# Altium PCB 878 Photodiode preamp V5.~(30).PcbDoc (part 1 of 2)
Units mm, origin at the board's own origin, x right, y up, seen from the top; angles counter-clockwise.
Board outline 114 x 114 mm, 6 copper layers (Top Layer, Internal Plane 1, Dummy Ground, Dummy Power, Internal Plane 2, Bottom Layer), stack 0.534 mm thick; 182 components, 80 nets, 485 pads, 76 vias.
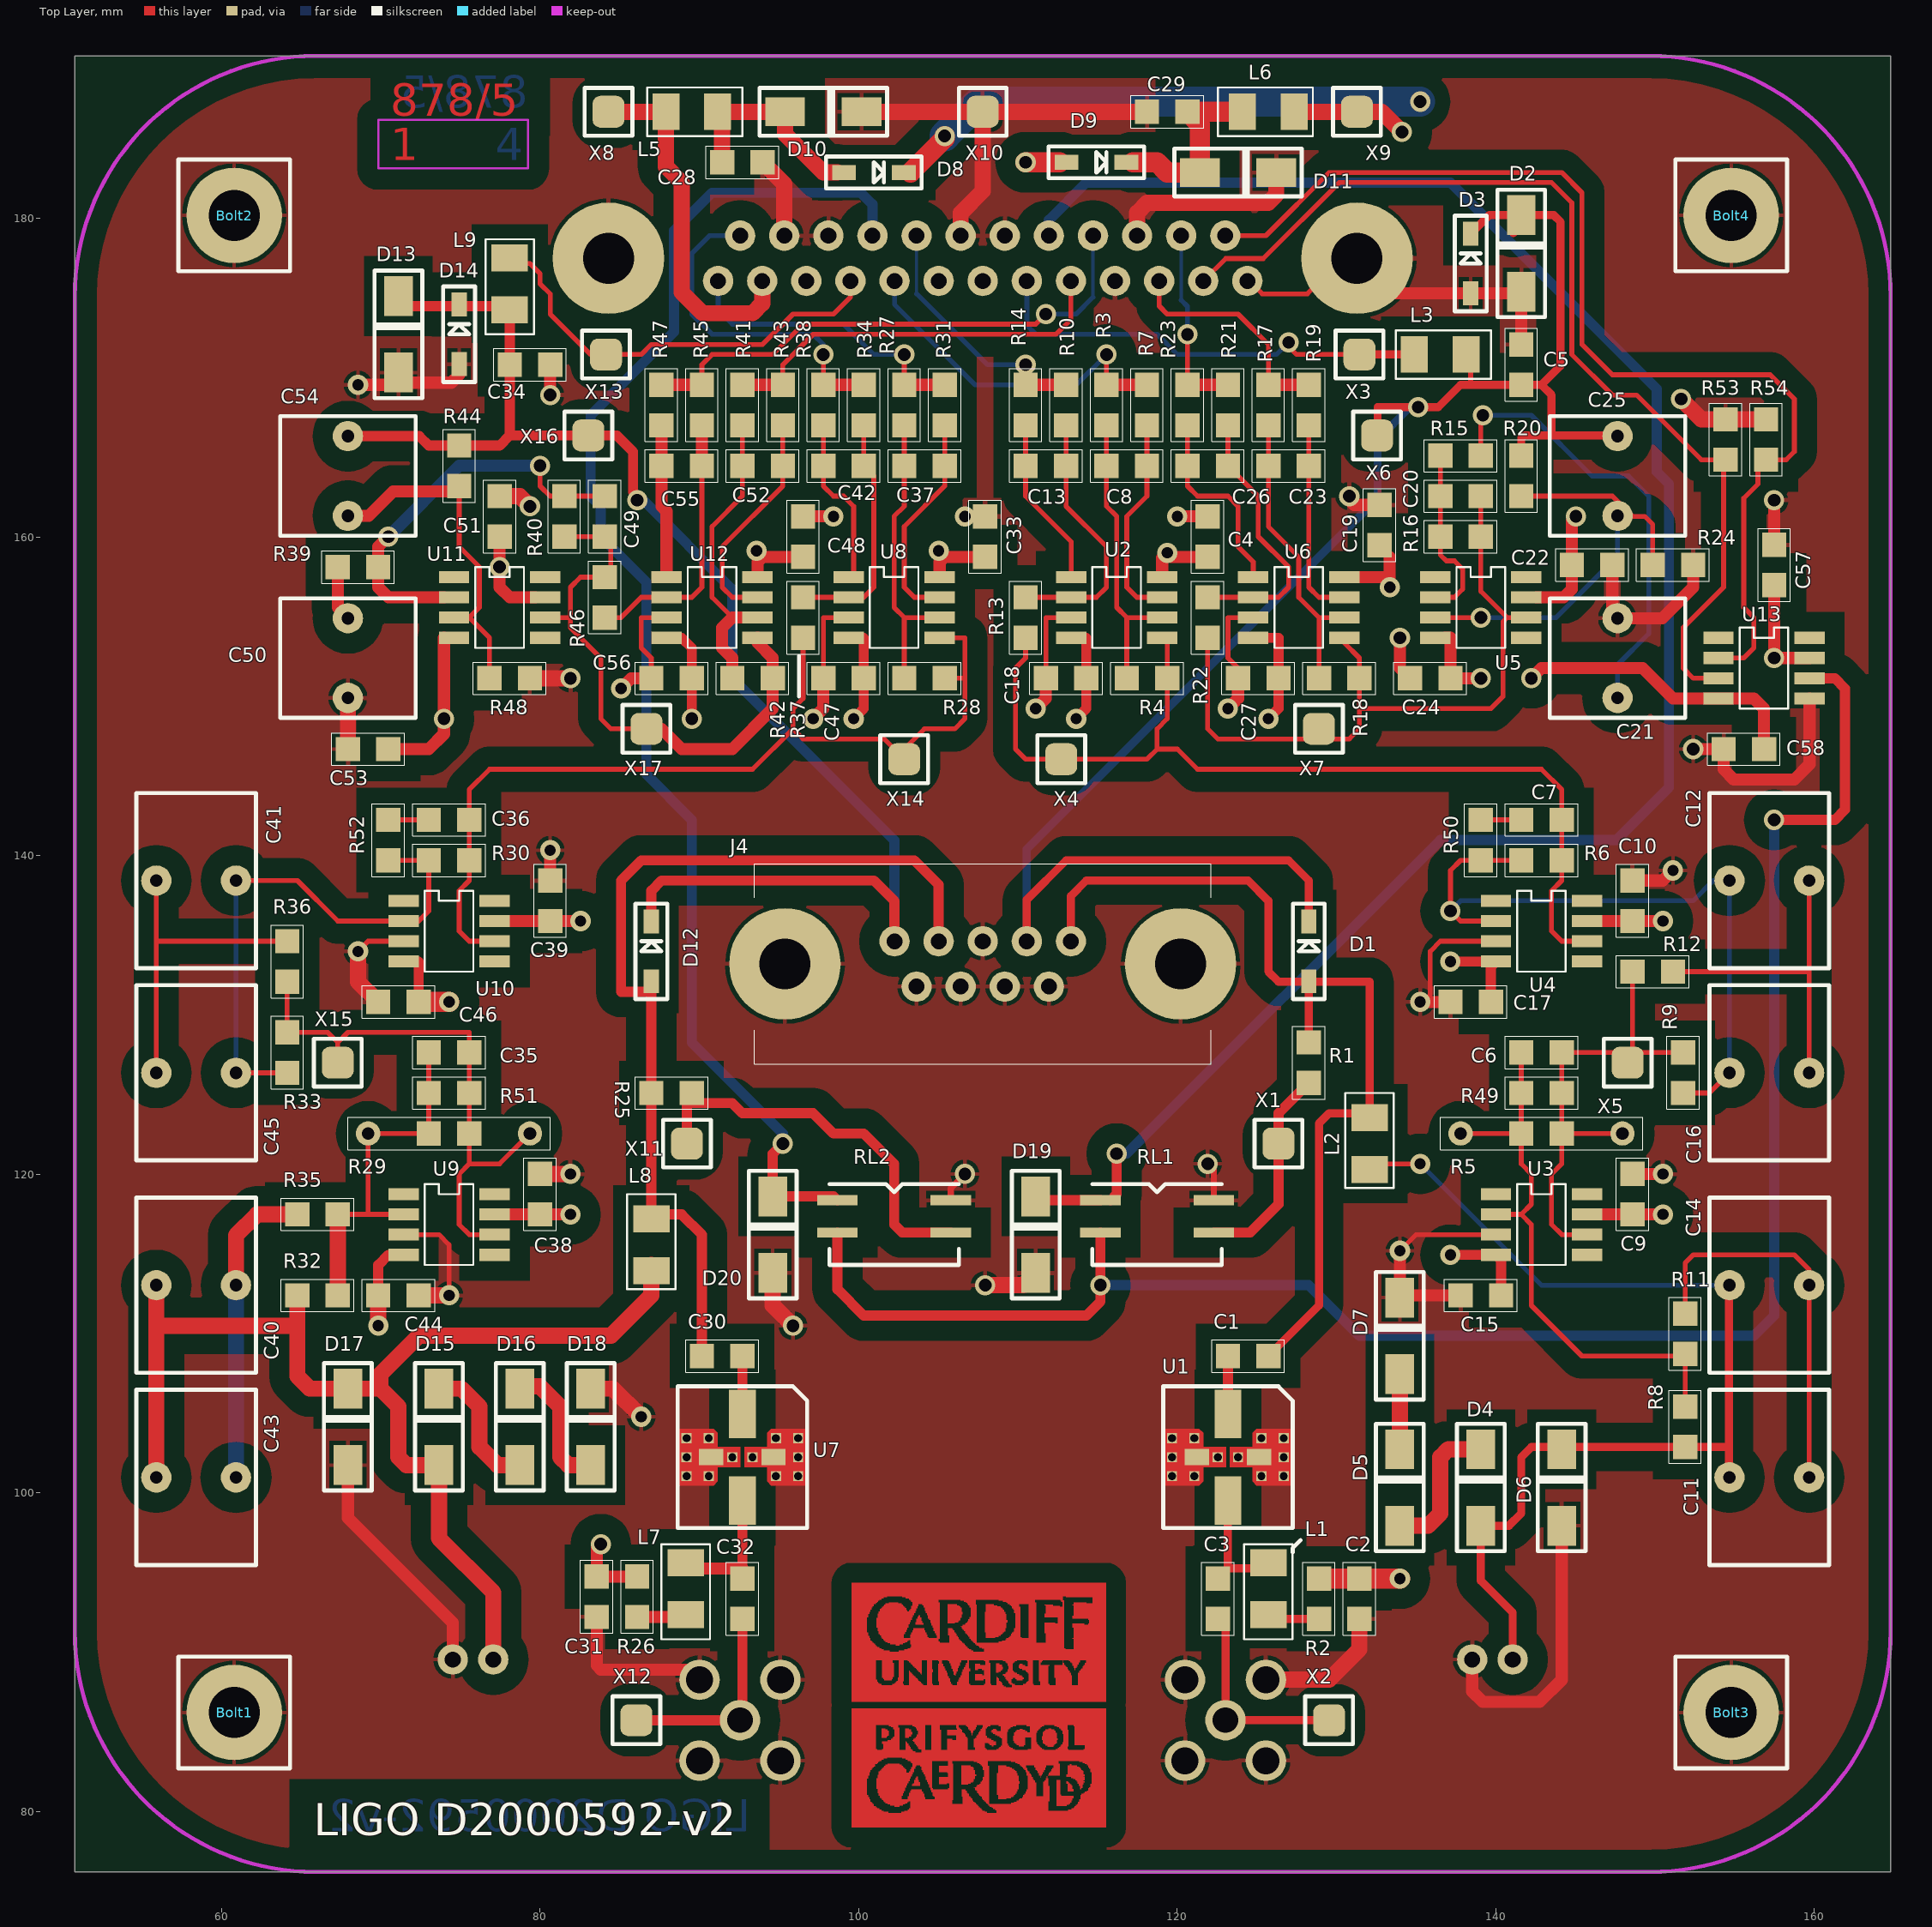
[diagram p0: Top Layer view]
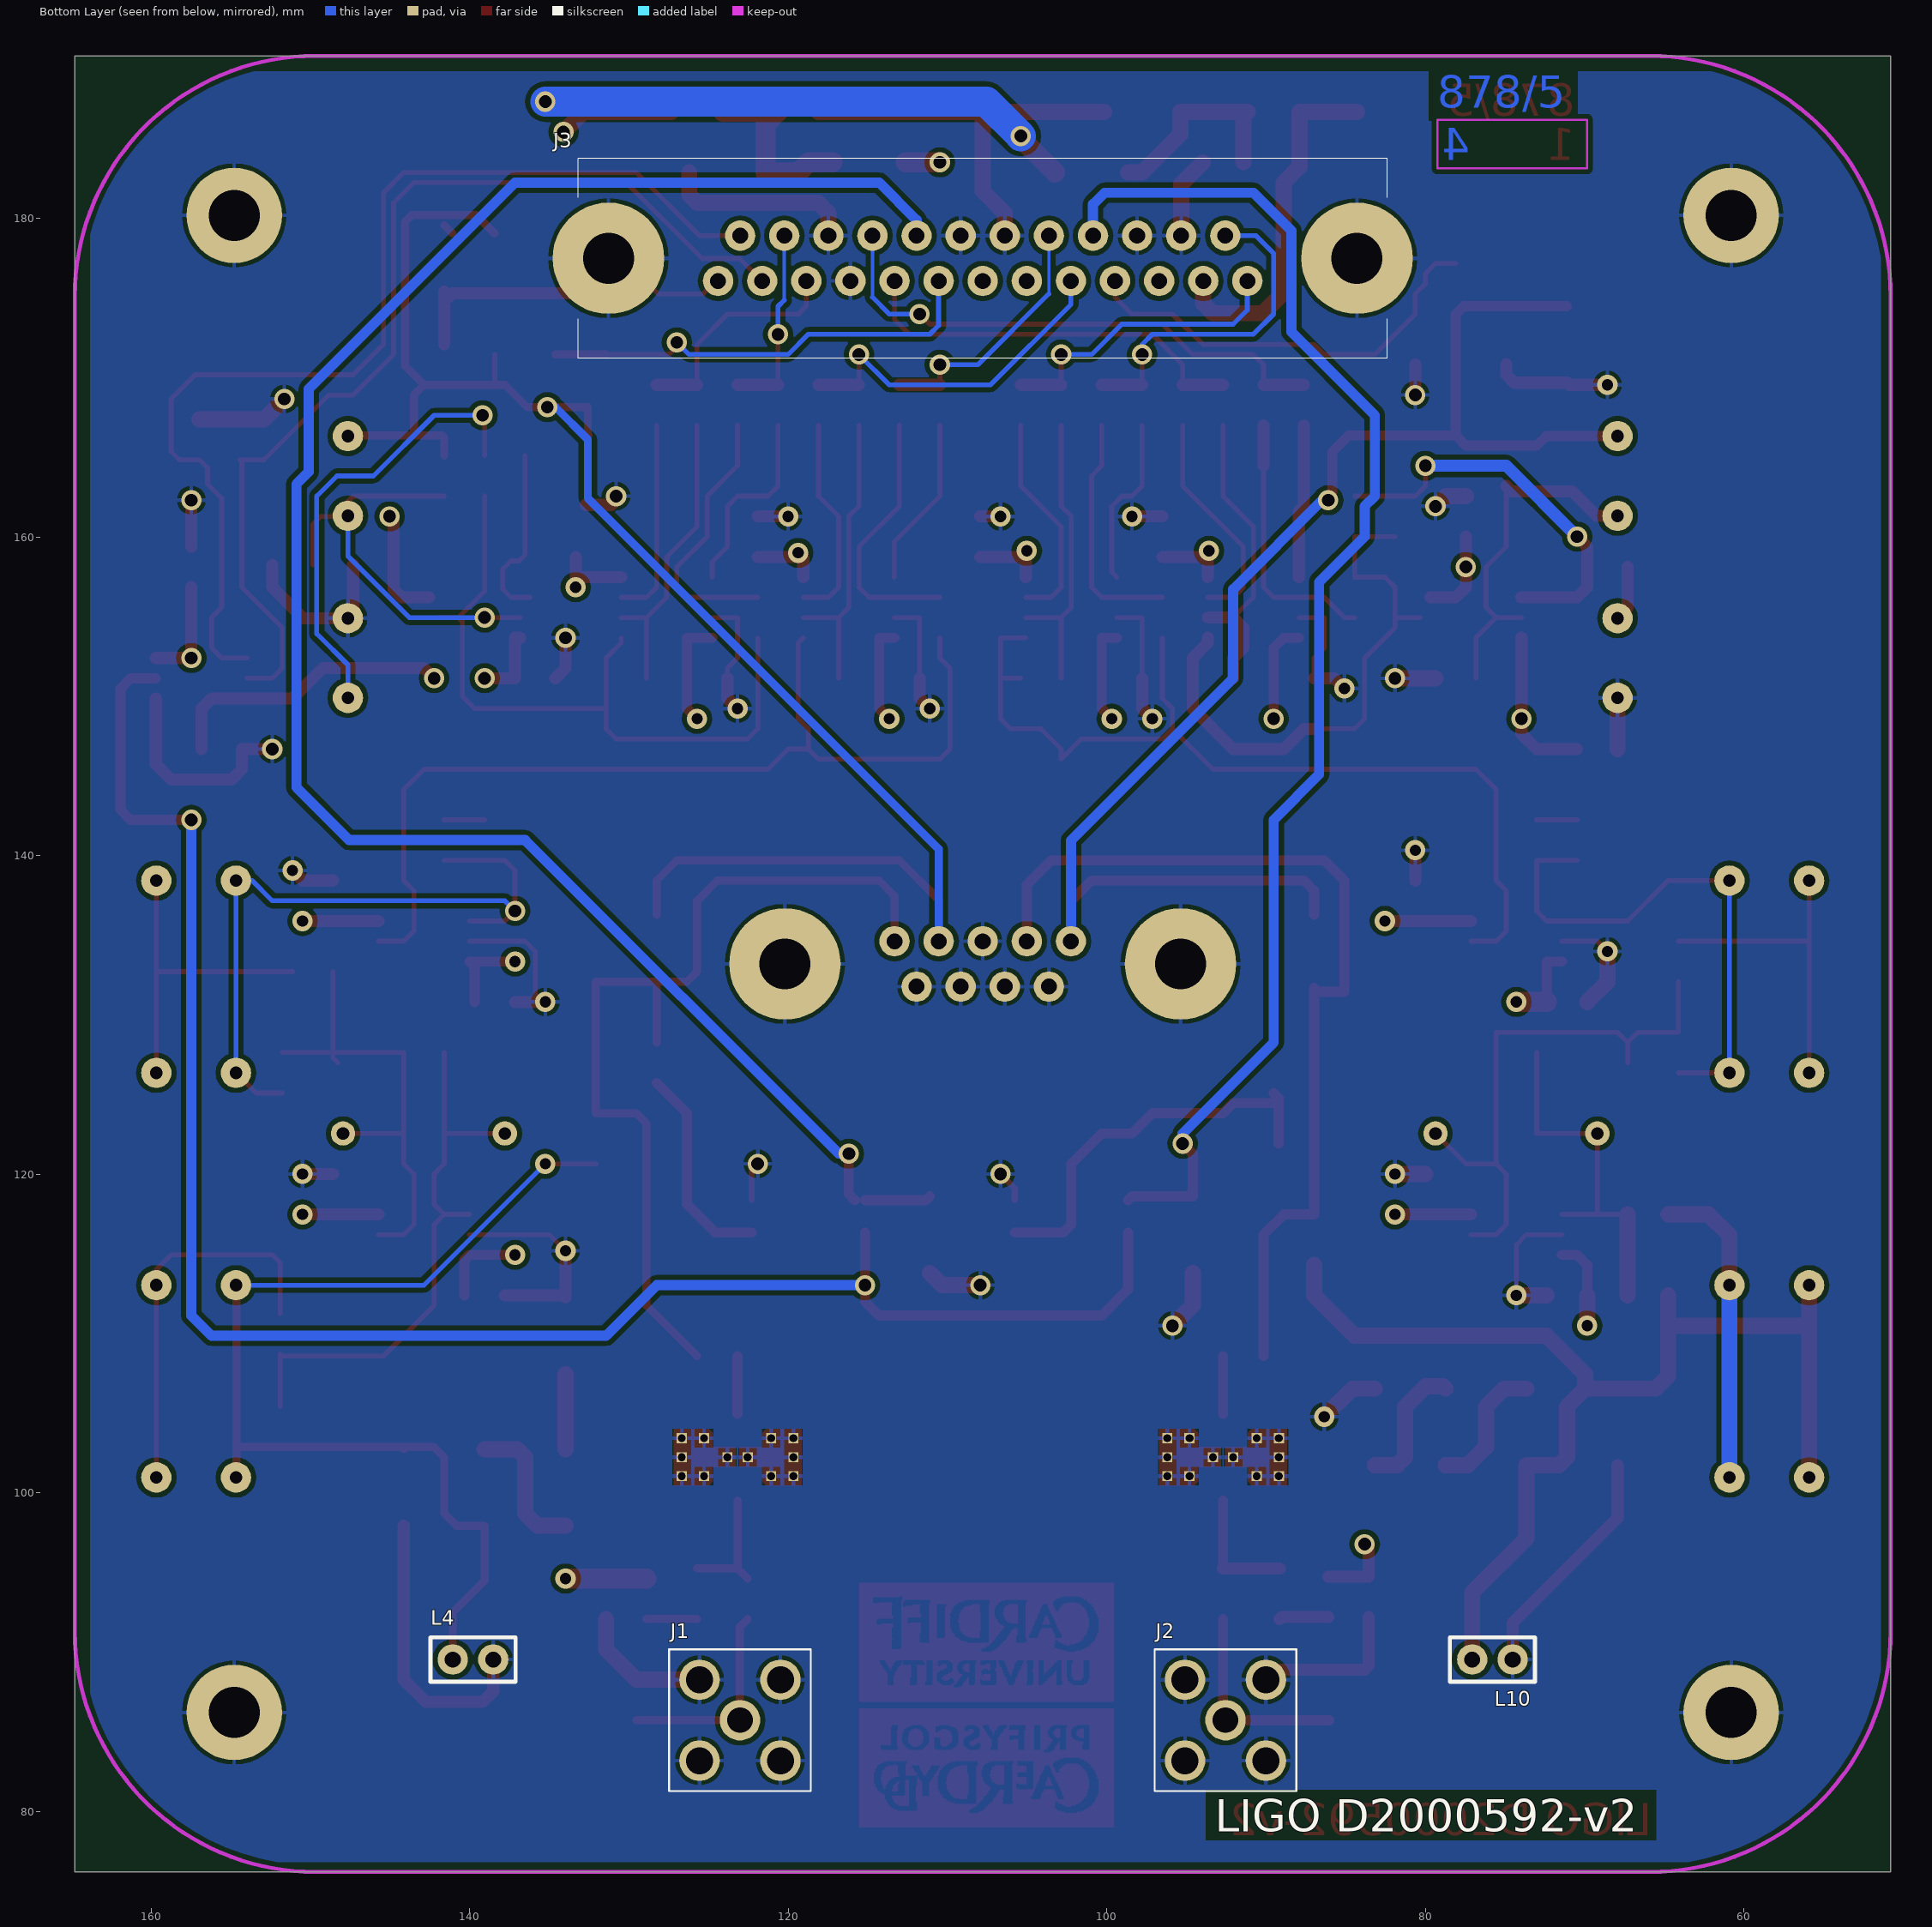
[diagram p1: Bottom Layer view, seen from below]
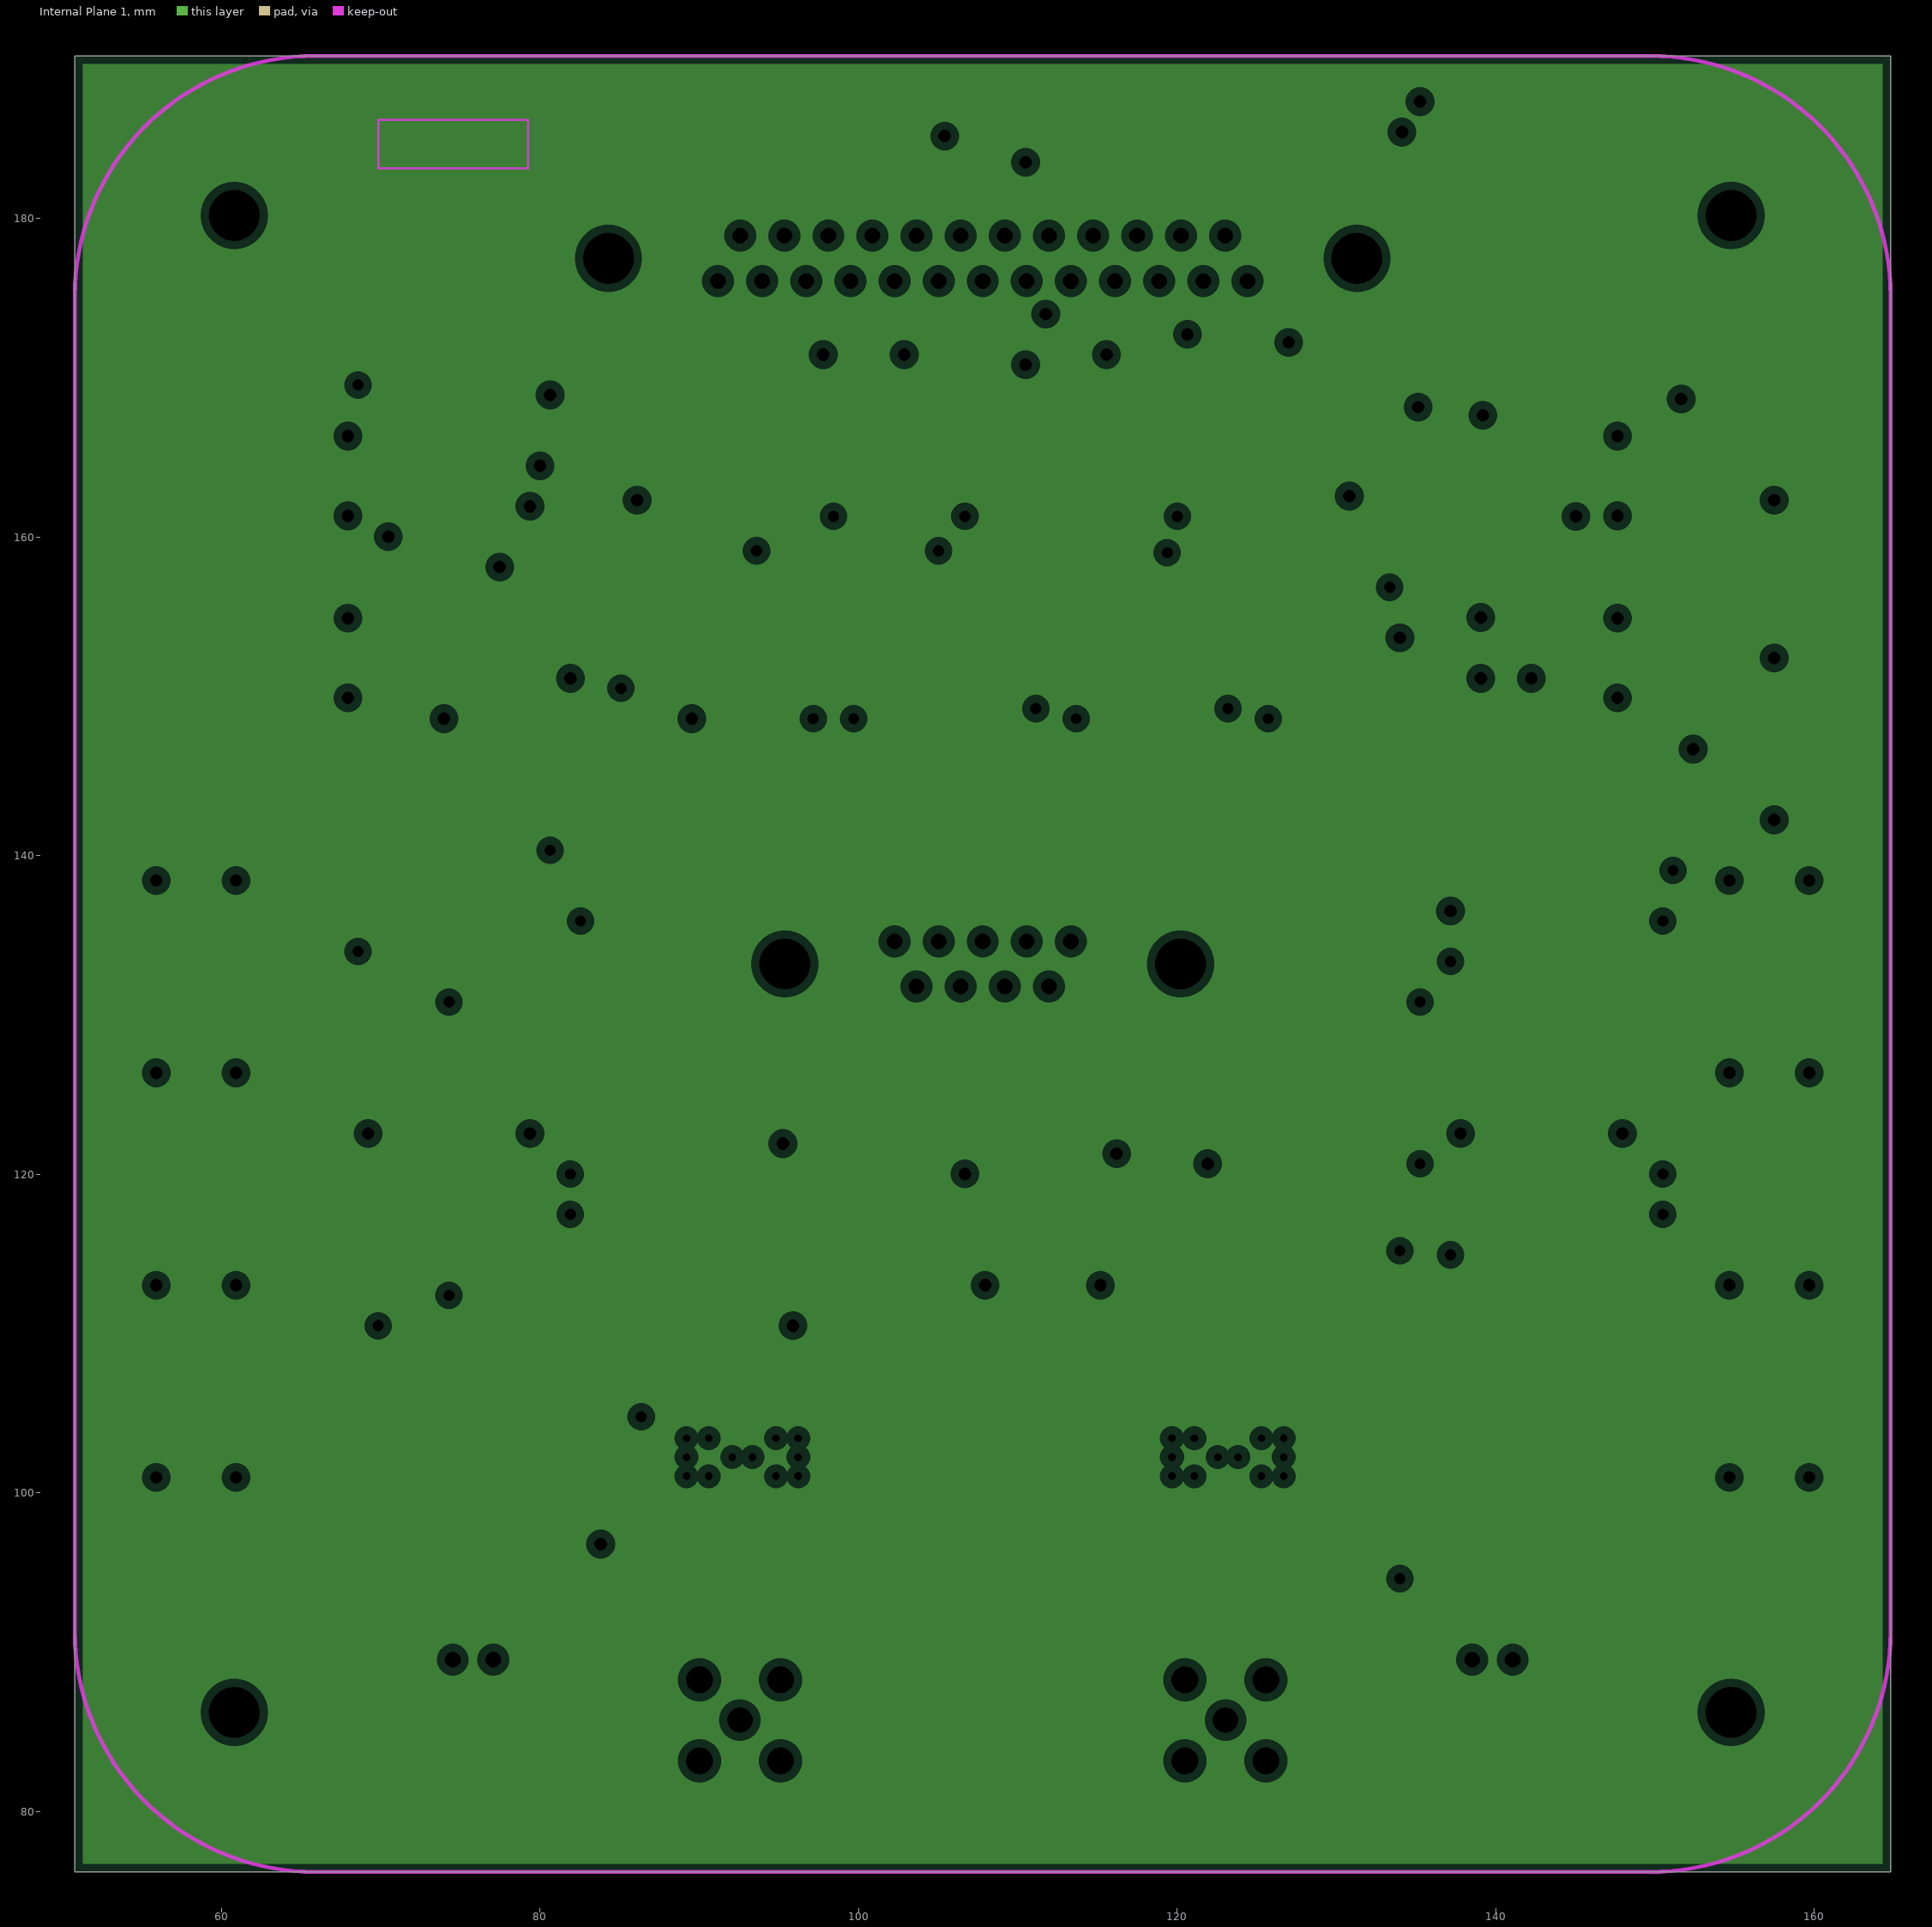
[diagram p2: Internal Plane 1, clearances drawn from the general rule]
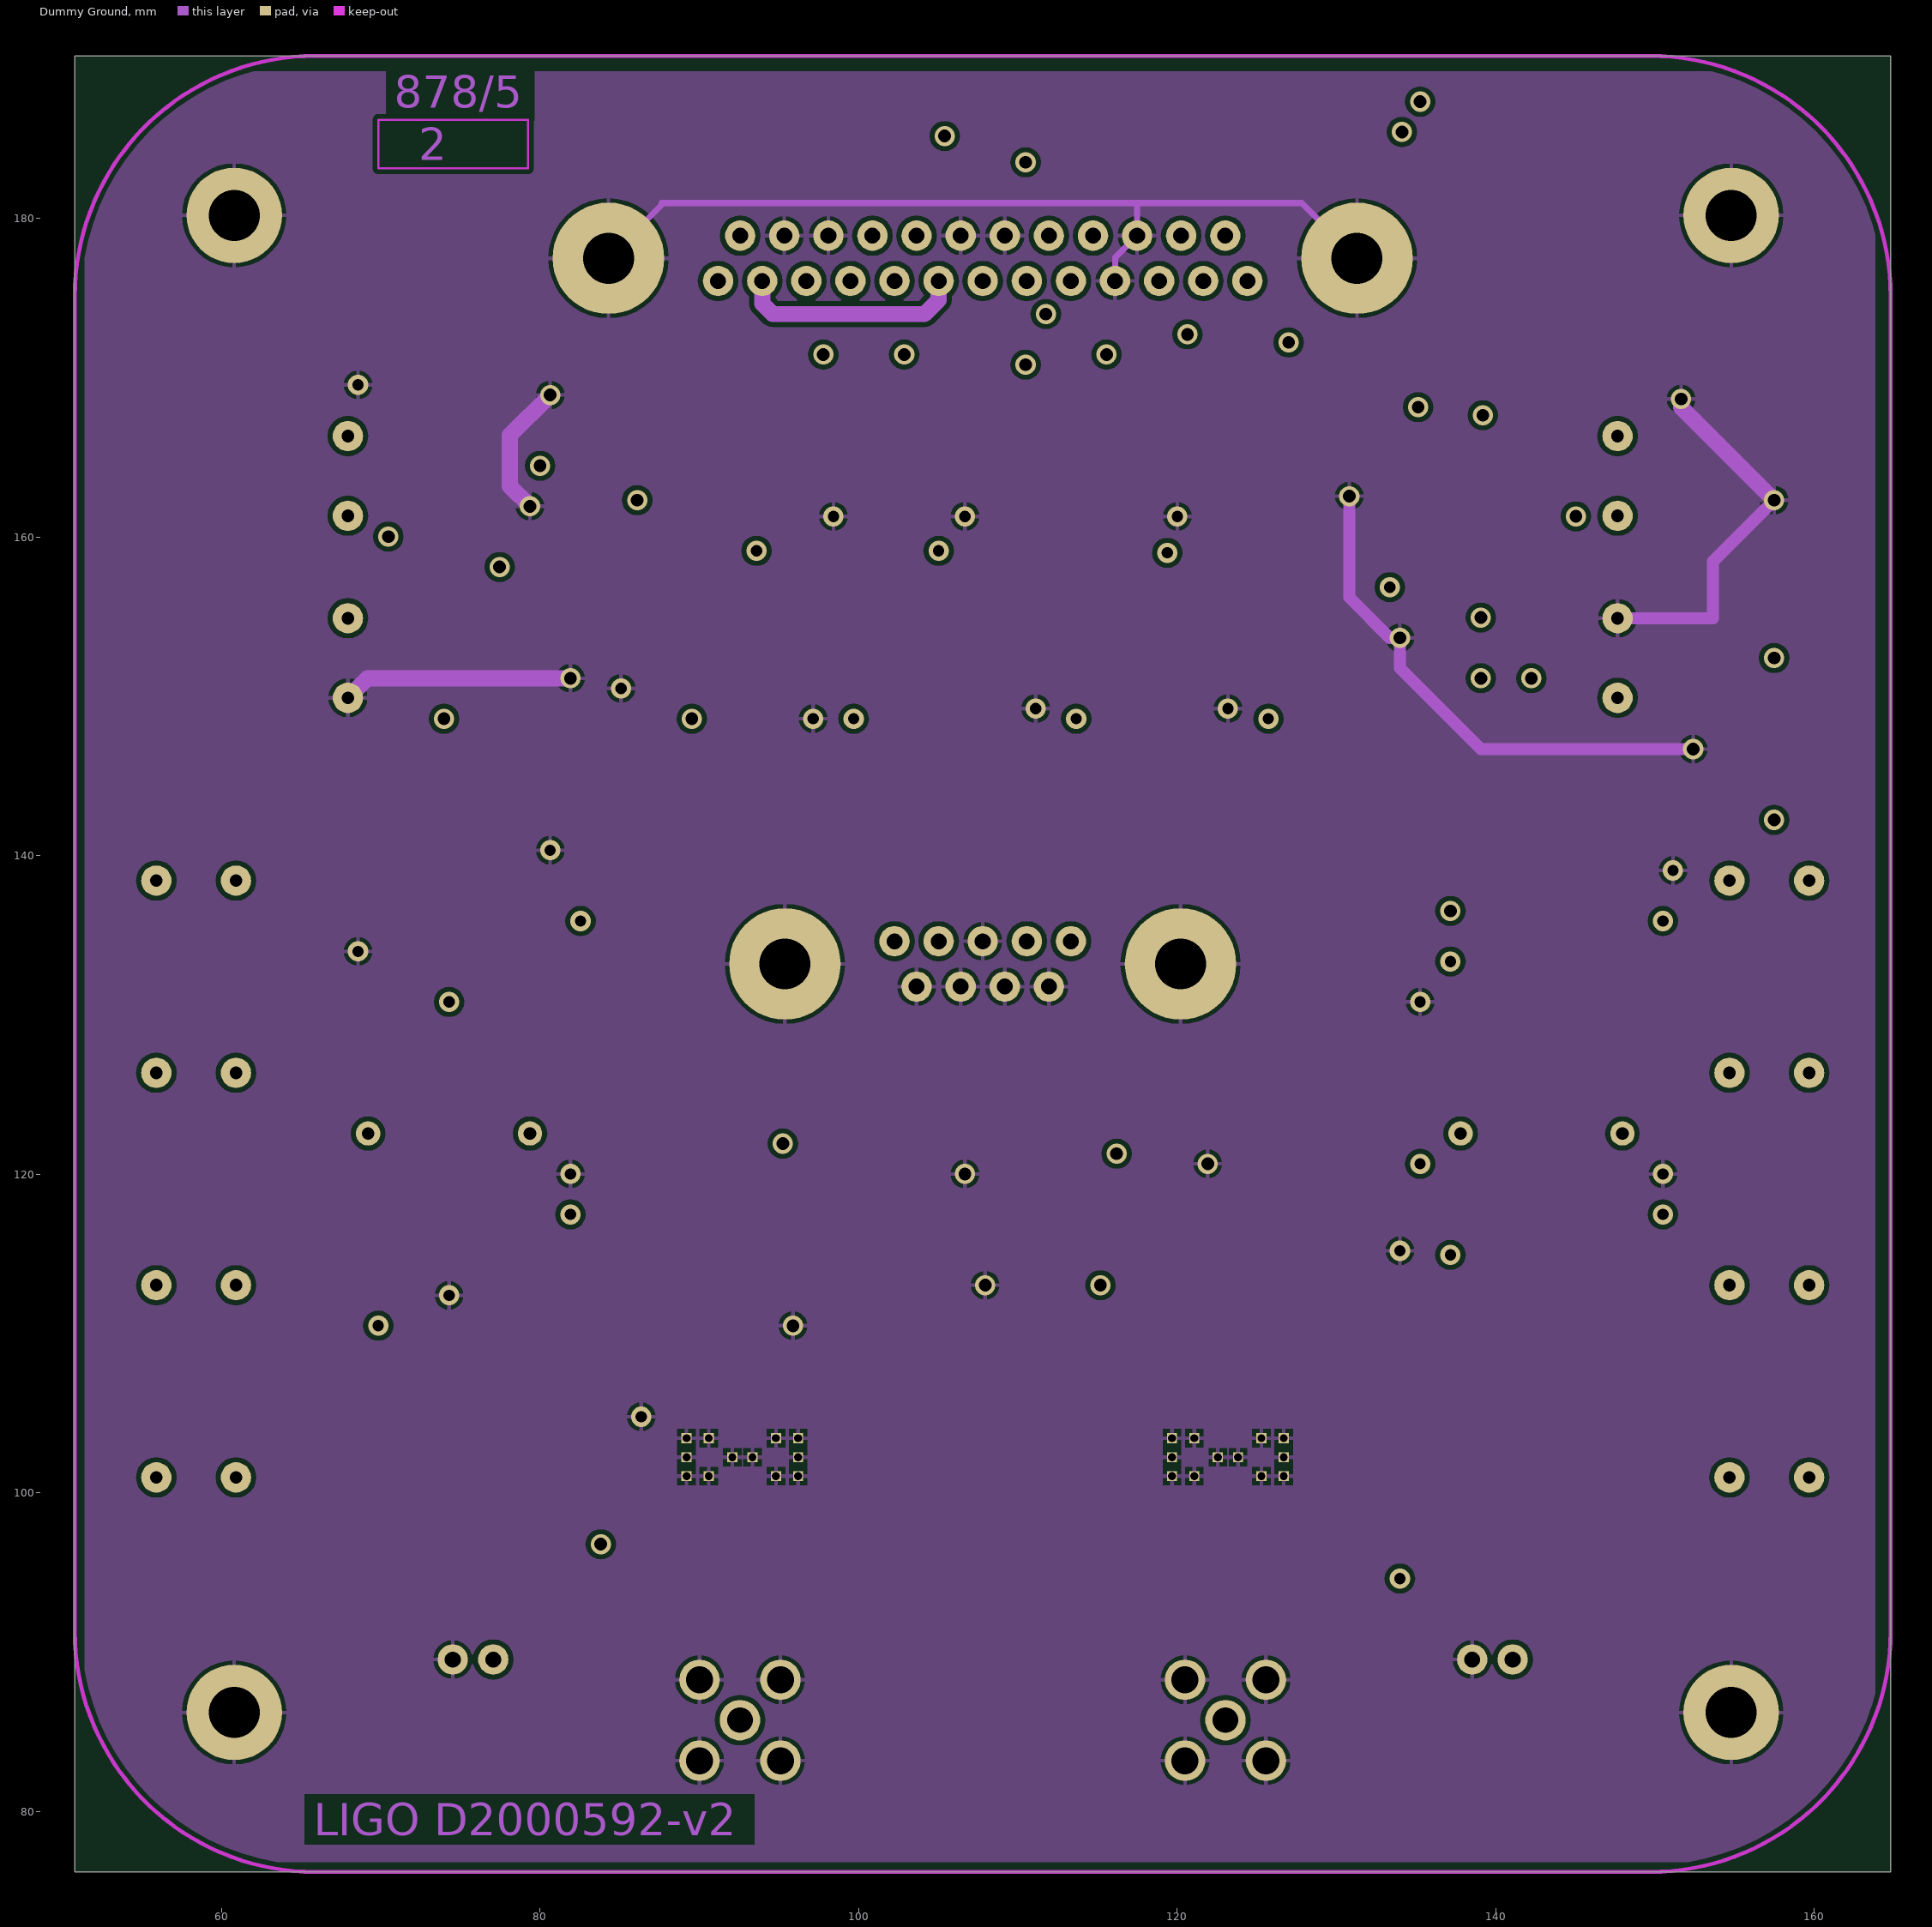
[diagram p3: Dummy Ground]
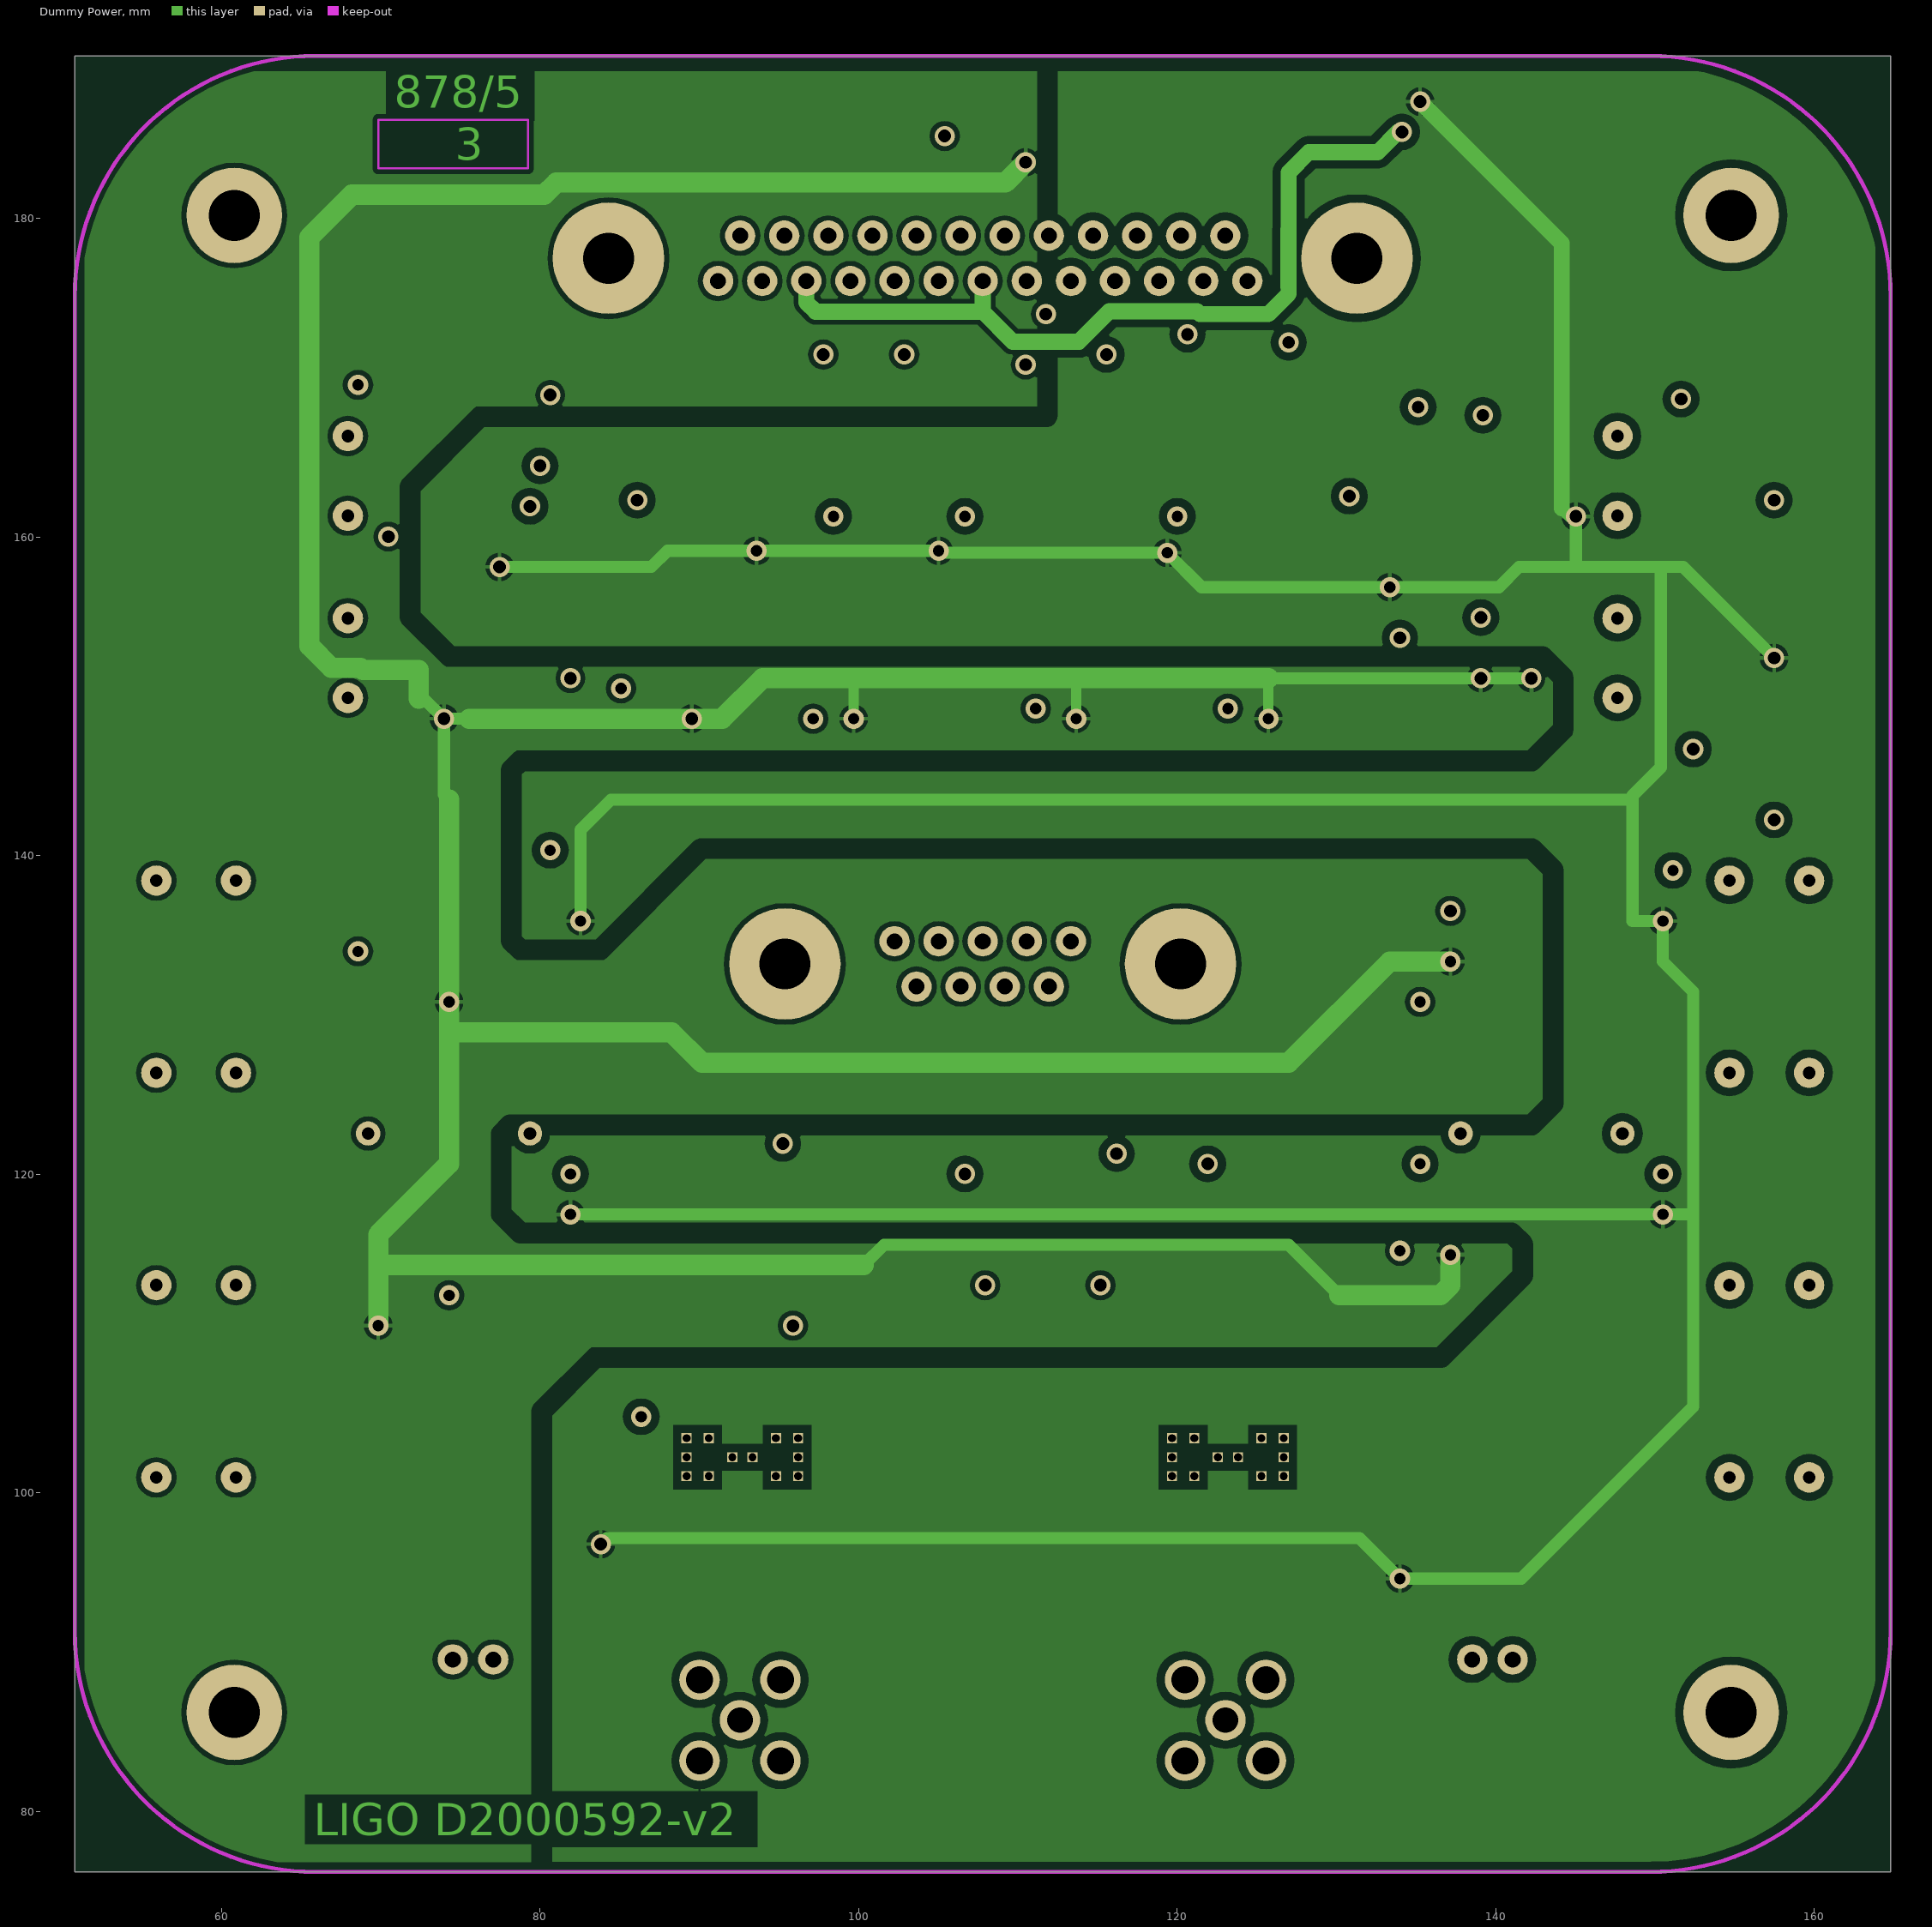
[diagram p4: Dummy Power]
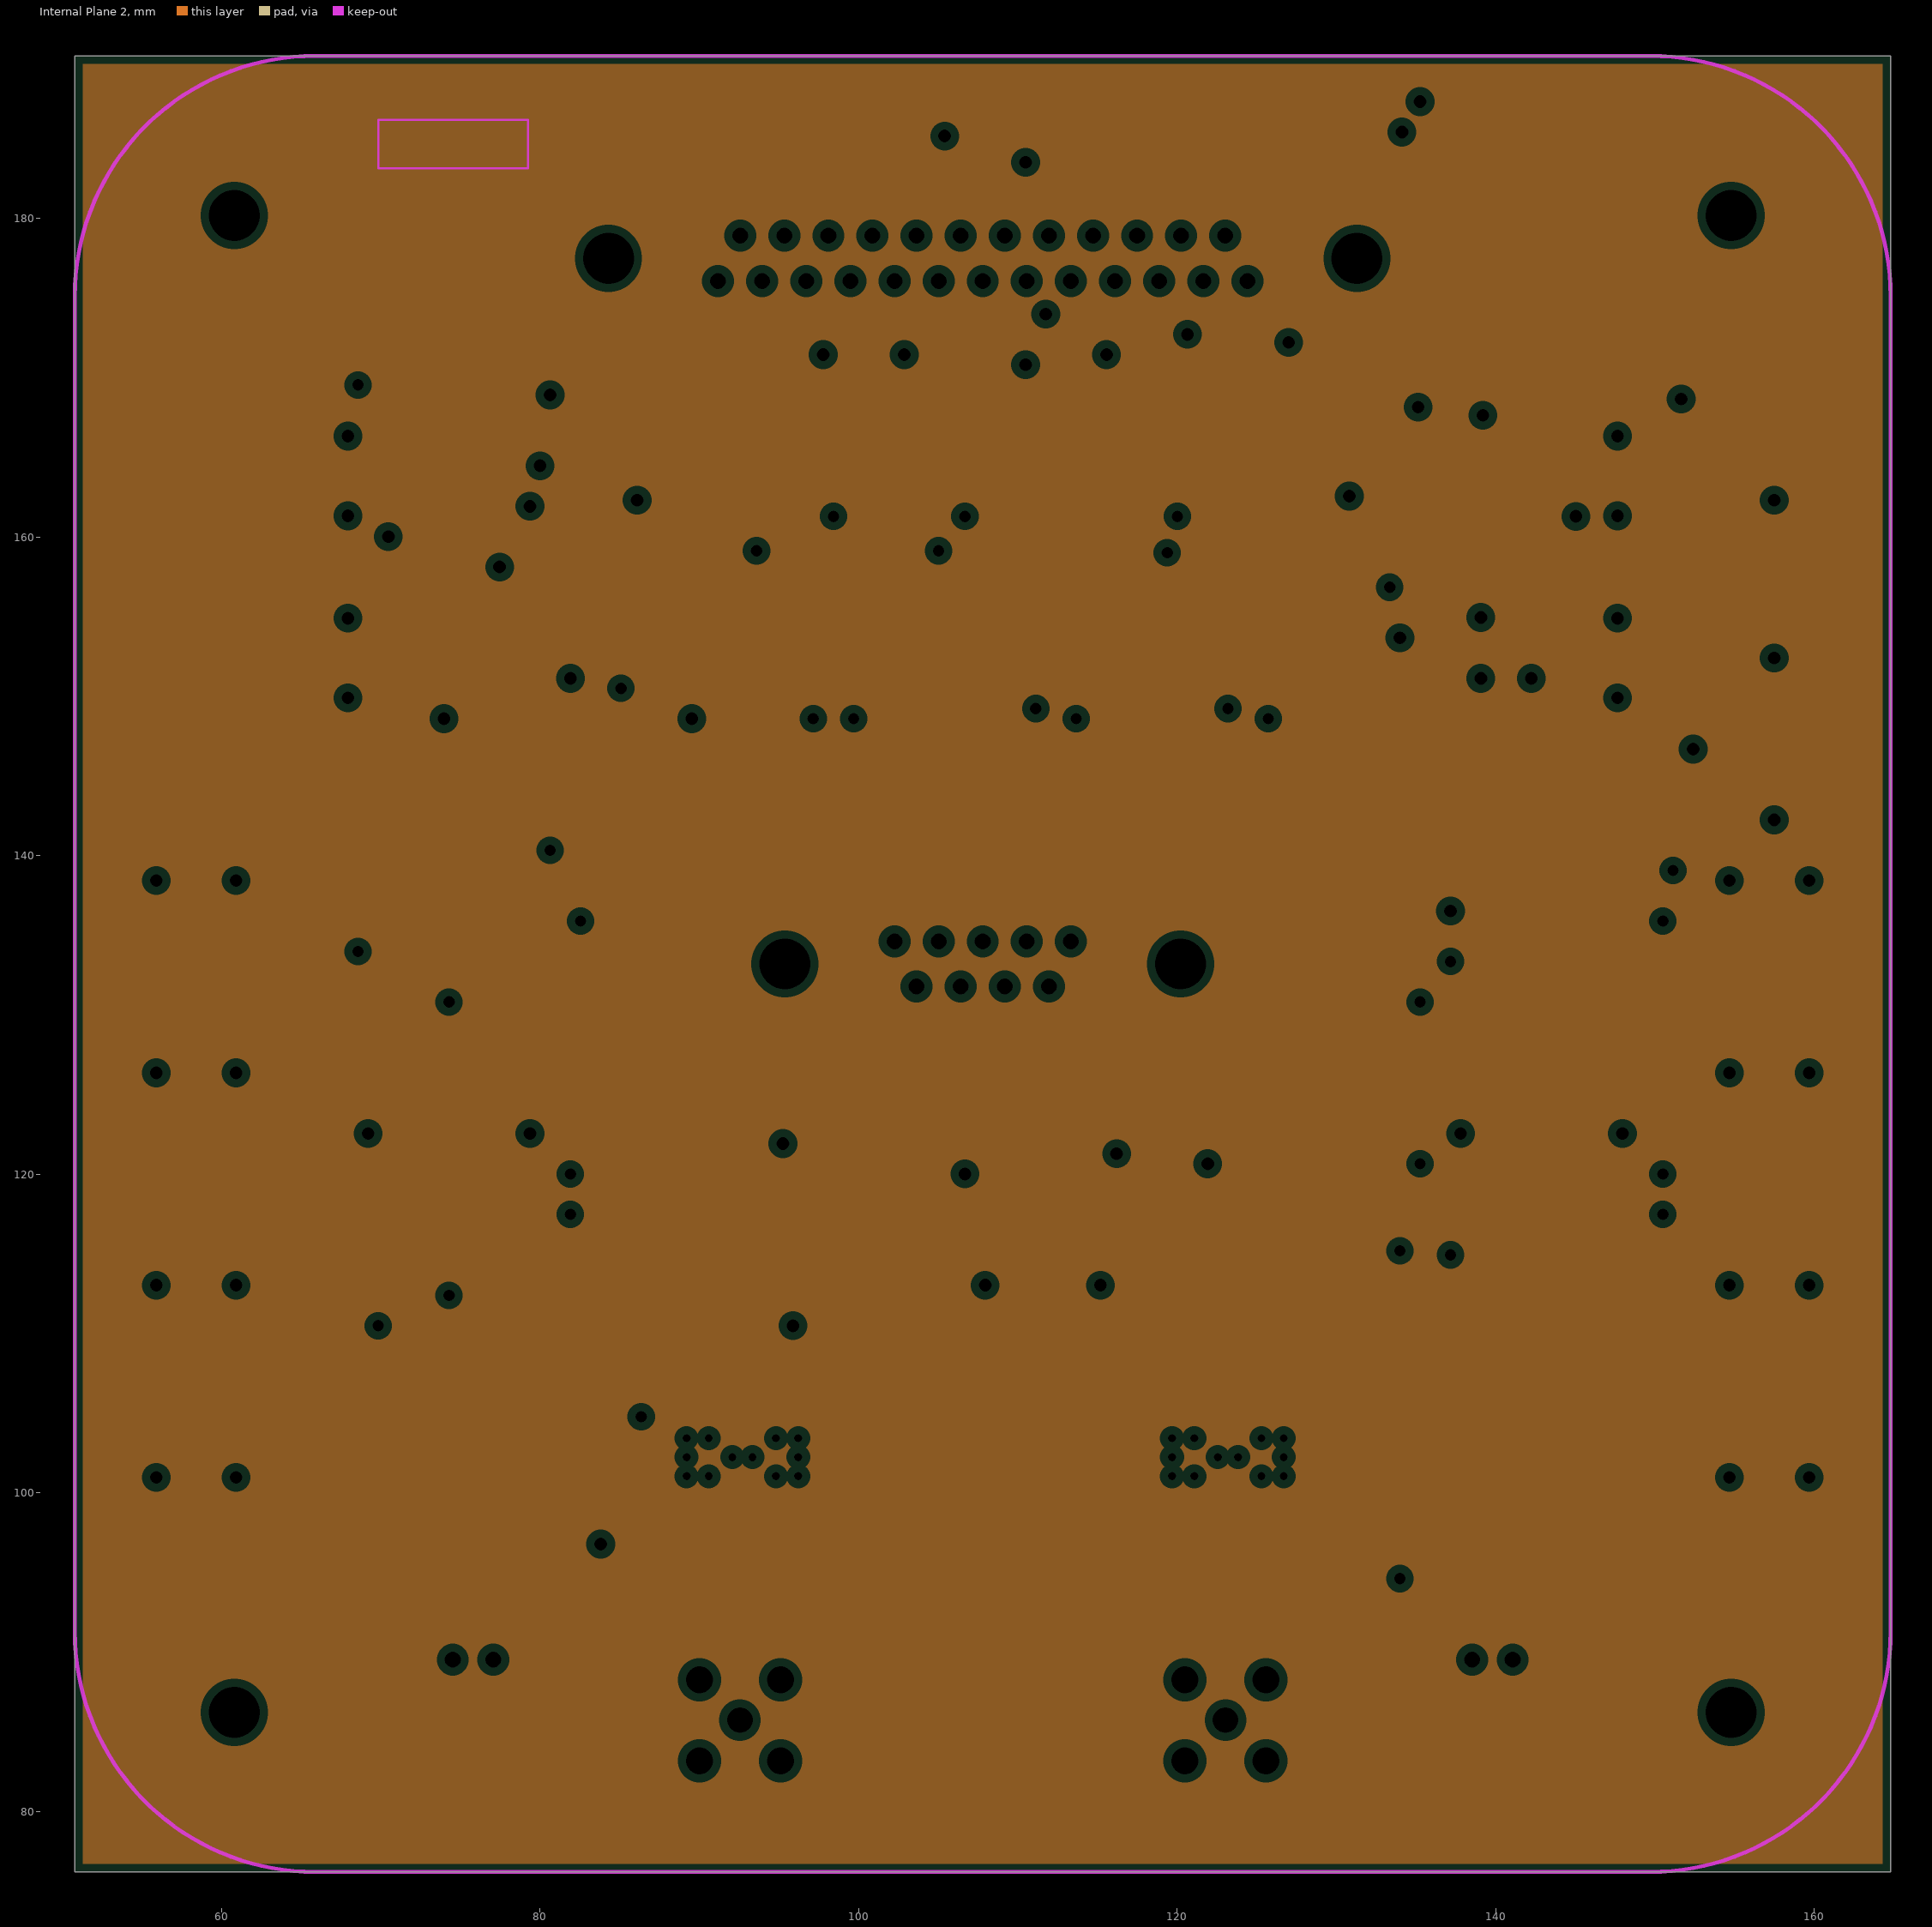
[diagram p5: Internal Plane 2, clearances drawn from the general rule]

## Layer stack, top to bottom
Top Solder: solder mask 0.0102, Solder Resist, Dk 3.5
Top Layer: signal copper 0.0356
Internal Plane 1: plane copper 0.0356
Dummy Ground: signal copper 0.036
Dummy Power: signal copper 0.036
Internal Plane 2: plane copper 0.0356
Dielectric 1: dielectric 0.32, FR-4, Dk 4.8
Bottom Layer: signal copper 0.0356
Bottom Solder: solder mask 0.0102, Solder Resist, Dk 3.5

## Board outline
50.8,76.2 164.795,76.2 164.795,190.195 50.8,190.195

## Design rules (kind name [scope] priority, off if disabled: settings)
Clearance Clearance_2 [InNamedPolygon('Top Layer-GND')] p1: gap=1.27 ignorepadtopadclearanceinfootprint=FALSE
Clearance Clearance_1 [(InNamedPolygon('+15V_L04_P006'))] p2: gap=0.508 ignorepadtopadclearanceinfootprint=FALSE
Clearance [All] p3: gap=0.305 ignorepadtopadclearanceinfootprint=FALSE
DiffPairsRouting [All] p1: maxlimit=0.254 minlimit=0.254 mostfreqgap=0.254 substack1={0A9BB5CB-1219-45DA-9E74-34527079F74E} toplayer_{0a9bb5cb-1219-45da-9e74-34527079f74e}_minwidth=0.381 toplayer_{0a9bb5cb-1219-45da-9e74-34527079f74e}_maxwidth=0.381 toplayer_{0a9bb5cb-1219-45da-9e74-34527079f74e}_prefwidth=0.381 midlayer1_{0a9bb5cb-1219-45da-9e74-34527079f74e}_minwidth=0.381 midlayer1_{0a9bb5cb-1219-45da-9e74-34527079f74e}_maxwidth=0.381 midlayer1_{0a9bb5cb-1219-45da-9e74-34527079f74e}_prefwidth=0.381 midlayer2_{0a9bb5cb-1219-45da-9e74-34527079f74e}_minwidth=0.381 midlayer2_{0a9bb5cb-1219-45da-9e74-34527079f74e}_maxwidth=0.381 midlayer2_{0a9bb5cb-1219-45da-9e74-34527079f74e}_prefwidth=0.381 bottomlayer_{0a9bb5cb-1219-45da-9e74-34527079f74e}_minwidth=0.381 bottomlayer_{0a9bb5cb-1219-45da-9e74-34527079f74e}_maxwidth=0.381 bottomlayer_{0a9bb5cb-1219-45da-9e74-34527079f74e}_prefwidth=0.381 toplayer_minwidth=0.381 toplayer_maxwidth=0.381 toplayer_prefwidth=0.381 midlayer1_minwidth=0.381 midlayer1_maxwidth=0.381 midlayer1_prefwidth=0.381 midlayer2_minwidth=0.381 midlayer2_maxwidth=0.381 midlayer2_prefwidth=0.381 bottomlayer_minwidth=0.381 bottomlayer_maxwidth=0.381 bottomlayer_prefwidth=0.381 maxuncoupledlength=12.7
HoleSize [All] p1: absolutevalues=TRUE maxlimit=3.81 minlimit=0.025 maxpercent=80.000 minpercent=20.000
PlaneClearance [All] p1: clearance=0.508
PlaneConnect [All] p1: planeconnectstyle=Relief reliefexpansion=0.508 reliefentries=4 reliefconductorwidth=0.254 reliefairgap=0.254
PolygonConnect [All] p1: connectstyle=Relief reliefconductorwidth=0.254 reliefentries=4 polygonreliefangle="90 Angle" airgapwidth=0.254
RoomDefinition "878 Photodiode preamp v5 P2" [InComponentClass('878 Photodiode preamp v5 P2')] p1: confinementstyle=ConfineIn formatcopy=TRUE lockcomponents=FALSE outline 0,0 50.8,0 50.8,25.4 0,25.4
RoomDefinition "878 Photodiode preamp v5 P1" [InComponentClass('878 Photodiode preamp v5 P1')] p2: confinementstyle=ConfineIn formatcopy=TRUE lockcomponents=FALSE outline 0,0 50.8,0 50.8,25.4 0,25.4
RoutingVias [All] p1: holewidth=0.8 width=1.27 viastyle="Through Hole" minholewidth=0.5 minwidth=0.762 maxholewidth=0.8 maxwidth=1.524
SilkToSilkClearance [All] p1: silktosilkclearance=0.127
SilkToSolderMaskClearance [IsPad] p1: minsilkscreentomaskgap=0.076 clearancetoexposedcopper=TRUE
SolderMaskExpansion [All] p1: expansion=0.102 istentingtop=FALSE
Width [All] p1: maxlimit=5.08 minlimit=0.203 preferedwidth=0.305 substack1={0A9BB5CB-1219-45DA-9E74-34527079F74E}
24 further rules are at their usual default settings.

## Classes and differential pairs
component class "878 Photodiode preamp v5 P2": C30 C31 C32 C33 C34 C35 C36 C37 C38 C39 C40 C41 C42 C43 C44 C45 C46 C47 C48 C49 C50 C51 C52 C53 C54 C55 C56 D12 D13 D14 D15 D16 D17 D18 D20 J2 J3 J4 L7 L8 L9 L10 R25 R26 R27 R28 R29 R30 R31 R32 R33 R34 R35 R36 R37 R38 R39 R40 R41 R42 R43 R44 R45 R46 R47 R48 R51 R52 RL2 U7 U8 U9 U10 U11 U12 X11 X12 X13 X14 X15 X16 X17
component class "878 Photodiode preamp v5 P1": Bolt1 Bolt2 Bolt3 Bolt4 C1 C2 C3 C4 C5 C6 C7 C8 C9 C10 C11 C12 C13 C14 C15 C16 C17 C18 C19 C20 C21 C22 C23 C24 C25 C26 C27 C28 C29 C57 C58 D1 D2 D3 D4 D5 D6 D7 D8 D9 D10 D11 D19 J1 L1 L2 L3 L4 L5 L6 R1 R2 R3 R4 R5 R6 R7 R8 R9 R10 R11 R12 R13 R14 R15 R16 R17 R18 R19 R20 R21 R22 R23 R24 R49 R50 R53 R54 RL1 U1 U2 U3 U4 U5 U6 U13 X1 X2 X3 X4 X5 X6 X7 X8 X9 X10

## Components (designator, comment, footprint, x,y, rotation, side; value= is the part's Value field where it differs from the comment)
Bolt1 "Bolt M3" BOLT 60.808,86.208 r0 top
Bolt2 "Bolt M3" BOLT 60.808,180.188 r0 top
Bolt3 "Bolt M3" BOLT 154.788,86.208 r0 top
Bolt4 "Bolt M3" BOLT 154.788,180.188 r0 top
C1 "Cap200" HS0805Long 124.46,108.585 r180 top value=4n7
C2 "Cap200" HS0805Long 131.445,93.345 r270 top value=100nF
C3 "Cap200" HS0805Long 122.555,93.345 r270 top value=10nF
C4 "Cap200" HS0805Long 121.92,160.02 r90 top value=100nF
C5 "Cap200" HS0805Long 141.605,170.815 r90 top value=1uF
C6 "Cap200" HS0805Long 142.875,127.635 r0 top value=1n5
C7 "Cap200" HS0805Long 142.875,142.24 r0 top value=15nF
C8 "Cap200" HS0805Long 116.84,164.465 r0 top value=220pF
C9 "Cap200" HS0805Long 148.59,118.745 r90 top value=100nF
C10 "Cap200" HS0805Long 148.59,137.16 r90 top value=100nF
C11 "Cap200" "MKS2 7.2 11" 157.175,100.965 r0 top value=10uF
C12 "Cap200" "MKS2 7.2 11" 157.175,138.43 r180 top value=10uF
C13 "Cap200" HS0805Long 111.76,164.465 r180 top value=220pF
C14 "Cap200" "MKS2 7.2 11" 157.175,113.03 r0 top value=10uF
C15 "Cap200" HS0805Long 139.065,112.395 r180 top value=100nF
C16 "Cap200" "MKS2 7.2 11" 157.175,126.365 r180 top value=10uF
C17 "Cap200" HS0805Long 138.43,130.81 r180 top value=100nF
C18 "Cap200" HS0805Long 113.03,151.13 r180 top value=100nF
C19 "Cap200" HS0805Long 132.715,160.744 r90 top value=100nF
C20 "Cap200" HS0805Long 137.795,162.56 r0 top value=1.5nF
C21 "Cap200" "MKS2 7.2 8.5" 147.65,152.4 r270 top value=4u7
C22 "Cap200" HS0805Long 146.05,158.242 r0 top value=100nF
C23 "Cap200" HS0805Long 127,164.465 r0 top value=220pF
C24 "Cap200" HS0805Long 135.89,151.13 r180 top value=100nF
C25 "Cap200" "MKS2 7.2 8.5" 147.65,163.83 r270 top value=4u7
C26 "Cap200" HS0805Long 121.92,164.465 r180 top value=220pF
C27 "Cap200" HS0805Long 125.095,151.13 r180 top value=100nF
C28 "Cap200" HS0805Long 92.71,183.515 r0 top value=1uF
C29 "Cap200" HS0805Long 119.38,186.69 r180 top value=1uF
C30 "Cap200" HS0805Long 91.44,108.585 r0 top value=4n7
C31 "Cap200" HS0805Long 83.566,93.472 r270 top value=100nF
C32 "Cap200" HS0805Long 92.71,93.345 r270 top value=10nF
C33 "Cap200" HS0805Long 107.95,160.02 r90 top value=100nF
C34 "Cap200" HS0805Long 79.375,170.815 r0 top value=1uF
C35 "Cap200" HS0805Long 74.295,127.635 r0 top value=1n5
C36 "Cap200" HS0805Long 74.295,142.24 r0 top value=15nF
C37 "Cap200" HS0805Long 104.14,164.465 r0 top value=220pF
C38 "Cap200" HS0805Long 80.01,118.745 r90 top value=100nF
C39 "Cap200" HS0805Long 80.645,137.16 r90 top value=100nF
C40 "Cap200" "MKS2 7.2 11" 58.42,113.03 r0 top value=10uF
C41 "Cap200" "MKS2 7.2 11" 58.42,138.43 r0 top value=10uF
C42 "Cap200" HS0805Long 99.06,164.465 r180 top value=220pF
C43 "Cap200" "MKS2 7.2 11" 58.42,100.965 r0 top value=10uF
C44 "Cap200" HS0805Long 71.12,112.395 r0 top value=100nF
C45 "Cap200" "MKS2 7.2 11" 58.42,126.365 r0 top value=10uF
C46 "Cap200" HS0805Long 71.12,130.81 r180 top value=100nF
C47 "Cap200" HS0805Long 99.06,151.13 r180 top value=100nF
C48 "Cap200" HS0805Long 96.52,160.02 r90 top value=100nF
C49 "Cap200" HS0805Long 84.074,161.29 r270 top value=1.5nF
C50 "Cap200" "MKS2 7.2 8.5" 67.945,152.4 r90 top value=4u7
C51 "Cap200" HS0805Long 77.47,161.29 r90 top value=100nF
C52 "Cap200" HS0805Long 93.98,164.465 r0 top value=220pF
C53 "Cap200" HS0805Long 69.215,146.685 r180 top value=100nF
C54 "Cap200" "MKS2 7.2 8.5" 67.945,163.83 r270 top value=4u7
C55 "Cap200" HS0805Long 88.9,164.465 r180 top value=220pF
C56 "Cap200" HS0805Long 88.265,151.13 r180 top value=100nF
C57 "Cap200" HS0805Long 157.48,158.242 r270 top value=100nF
C58 "Cap200" HS0805Long 155.575,146.685 r180 top value=100nF
D1 "60V 1A" SOD123 128.27,133.985 r270 top
D2 "SMAJxxCA" DO214AC 141.605,177.8 r270 top
D3 "60V 1A" SOD123 138.43,177.165 r270 top
D4 "1N4007" DO214AC 139.065,100.33 r270 top
D5 "1N4007" DO214AC 133.985,100.33 r270 top
D6 "1N4007" DO214AC 144.145,100.33 r270 top
D7 "1N4007" DO214AC 133.985,109.855 r270 top
D8 "60V 1A" SOD123 100.965,182.88 r180 top
D9 "60V 1A" SOD123 114.935,183.515 r180 top
D10 "SMAJxxCA" DO214AC 97.79,186.69 r180 top
D11 "SMAJxxCA" DO214AC 123.825,182.88 r180 top
D12 "60V 1A" SOD123 86.995,133.985 r270 top
D13 "SMAJxxCA" DO214AC 71.12,172.72 r270 top
D14 "60V 1A" SOD123 74.93,172.72 r270 top
D15 "1N4007" DO214AC 73.66,104.14 r270 top
D16 "1N4007" DO214AC 78.74,104.14 r270 top
D17 "1N4007" DO214AC 67.945,104.14 r270 top
D18 "1N4007" DO214AC 83.185,104.14 r270 top
D19 "1N4004" DO214AC 111.125,116.205 r270 top
D20 "1N4004" DO214AC 94.615,116.205 r270 top
J1 "SMA" "PCB SMB" 123.038,85.725 r180 bottom
J2 "SMA" "PCB SMB" 92.558,85.725 r180 bottom
J3 "D connector 25 way" "D Socket Straight PCB 25 Way" 107.798,177.49 r0 bottom
J4 "D connector 9 way" "D Plug Straight PCB 9 Way" 107.798,133.198 r0 top
L1 "Inductor" HS1210 125.73,93.98 r270 top value=10uH
L2 "Inductor" HS1210 132.08,121.92 r90 top value=82uH
L3 "Inductor" HS1210 136.525,171.45 r0 top value=0Ohm
L4 "Inductor" "2 way 0.1\"" 139.795,89.535 r0 bottom value=2.6H
L5 "Inductor" HS1210 89.535,186.69 r0 top value=10uH
L6 "Inductor" HS1210 125.73,186.69 r180 top value=10uH
L7 "Inductor" HS1210 89.154,93.98 r270 top value=10uH
L8 "Inductor" HS1210 86.995,115.57 r90 top value=82uH
L9 "Inductor" HS1210 78.105,175.895 r270 top value=0Ohm
L10 "Inductor" "2 way 0.1\"" 75.8,89.535 r0 bottom value=2.6H
R1 "Res" hs0805long 128.27,127 r90 top value=100K
R2 "Res" hs0805long 128.905,93.345 r90 top value=680R
R3 "Res" hs0805long 115.57,168.275 r90 top value=1K
R4 "Res" hs0805long 118.11,151.13 r180 top value=1K
R5 "Res" SpecialR 142.875,122.555 r0 top value=10K
R6 "Res" hs0805long 142.875,139.7 r0 top value=1K
R7 "Res" hs0805long 118.11,168.275 r90 top value=10R
R8 "Res" hs0805long 151.892,104.14 r90 top value=3K1
R9 "Res" hs0805long 151.765,126.365 r270 top value=1K
R10 "Res" hs0805long 113.03,168.275 r90 top value=1K
R11 "Res" hs0805long 151.892,109.982 r270 top value=100R
R12 "Res" hs0805long 149.86,132.715 r0 top value=250R
R13 "Res" hs0805long 110.49,154.94 r90 top value=1K
R14 "Res" hs0805long 110.49,168.275 r90 top value=10R
R15 "Res" hs0805long 137.795,165.1 r0 top value=1K1
R16 "Res" hs0805long 137.795,160.02 r0 top value=10K
R17 "Res" hs0805long 125.73,168.275 r90 top value=1K
R18 "Res" hs0805long 130.175,151.13 r180 top value=1K
R19 "Res" hs0805long 128.27,168.275 r90 top value=10R
R20 "Res" hs0805long 141.605,163.83 r90 top value=10K
R21 "Res" hs0805long 123.19,168.275 r90 top value=1K
R22 "Res" hs0805long 121.92,154.94 r90 top value=1K
R23 "Res" hs0805long 120.65,168.275 r90 top value=10R
R24 "Res" hs0805long 151.13,158.242 r180 top value=1K1
R25 "Res" hs0805long 88.265,125.095 r180 top value=100K
R26 "Res" hs0805long 86.106,93.472 r90 top value=680R
R27 "Res" hs0805long 102.87,168.275 r90 top value=1K
R28 "Res" hs0805long 104.14,151.13 r180 top value=1K
R29 "Res" SpecialR 74.295,122.555 r0 top value=10K
R30 "Res" hs0805long 74.295,139.7 r0 top value=1K
R31 "Res" hs0805long 105.41,168.275 r90 top value=10R
R32 "Res" hs0805long 66.04,112.395 r0 top value=3K1
R33 "Res" hs0805long 64.135,127.635 r270 top value=1K
R34 "Res" hs0805long 100.33,168.275 r90 top value=1K
R35 "Res" hs0805long 66.04,117.475 r0 top value=100R
R36 "Res" hs0805long 64.135,133.35 r90 top value=250R
R37 "Res" hs0805long 96.52,154.94 r90 top value=1K
R38 "Res" hs0805long 97.79,168.275 r90 top value=10R
R39 "Res" hs0805long 68.58,158.115 r180 top value=1K1
R40 "Res" hs0805long 81.534,161.29 r270 top value=10K
R41 "Res" hs0805long 92.71,168.275 r90 top value=1K
R42 "Res" hs0805long 93.345,151.13 r180 top value=1K
R43 "Res" hs0805long 95.25,168.275 r90 top value=10R
R44 "Res" hs0805long 74.93,164.465 r90 top value=10K
R45 "Res" hs0805long 90.17,168.275 r90 top value=1K
R46 "Res" hs0805long 84.074,156.21 r270 top value=1K
R47 "Res" hs0805long 87.63,168.275 r90 top value=10R
R48 "Res" hs0805long 78.105,151.13 r180 top value=1K1
R49 "Res" hs0805long 142.875,125.095 r0 top value=-
R50 "Res" hs0805long 139.065,140.97 r90 top value=0R
R51 "Res" hs0805long 74.295,125.095 r0 top value=-
R52 "Res" hs0805long 70.485,140.97 r90 top value=0R
R53 "Res" HS0805Long 154.432,166.116 r270 top value=100K
R54 "Res" HS0805Long 156.972,166.116 r270 top value=100K
RL1 "9901 relay" "9901 Relay" 118.745,116.84 r0 top
RL2 "9901 relay" "9901 Relay" 102.235,116.84 r0 top
U1 "MAR-6SM" ww107 123.19,102.235 r180 top
U2 "AD8672ARZ" "SOIC 8" 116.205,155.575 r270 top
U3 "OPA209" "SOIC 8" 142.875,116.84 r270 top
U4 "LT1028" "SOIC 8" 142.875,135.255 r270 top
U5 "LT1028" "SOIC 8" 139.065,155.575 r270 top
U6 "AD8672ARZ" "SOIC 8" 127.635,155.575 r270 top
U7 "MAR-6SM" ww107 92.71,102.235 r180 top
U8 "AD8672ARZ" "SOIC 8" 102.235,155.575 r270 top
U9 "OPA209" "SOIC 8" 74.295,116.84 r270 top
U10 "LT1028" "SOIC 8" 74.295,135.255 r270 top
U11 "LT1028" "SOIC 8" 77.47,155.575 r270 top
U12 "AD8672ARZ" "SOIC 8" 90.805,155.575 r270 top
U13 "AD620" "SOIC 8" 156.845,151.765 r270 top
X1 "TestPoint" "SM Test point" 126.365,121.92 r0 top
X2 "TestPoint" "SM Test point" 129.54,85.725 r0 top
X3 "TestPoint" "SM Test point" 131.445,171.45 r90 top
X4 "TestPoint" "SM Test point" 112.725,146.05 r90 top
X5 "TestPoint" "SM Test point" 148.285,127 r90 top
X6 "TestPoint" "SM Test point" 132.554,166.37 r0 top
X7 "TestPoint" "SM Test point" 128.905,147.955 r0 top
X8 "TestPoint" "SM Test point" 84.303,186.69 r0 top
X9 "TestPoint" "SM Test point" 131.293,186.69 r0 top
X10 "TestPoint" "SM Test point" 107.798,186.69 r0 top
X11 "TestPoint" "SM Test point" 89.23,121.92 r0 top
X12 "TestPoint" "SM Test point" 86.055,85.725 r0 top
X13 "TestPoint" "SM Test point" 84.15,171.45 r0 top
X14 "TestPoint" "SM Test point" 102.87,146.05 r90 top
X15 "TestPoint" "SM Test point" 67.31,127 r90 top
X16 "TestPoint" "SM Test point" 83.041,166.37 r0 top
X17 "TestPoint" "SM Test point" 86.69,147.955 r0 top

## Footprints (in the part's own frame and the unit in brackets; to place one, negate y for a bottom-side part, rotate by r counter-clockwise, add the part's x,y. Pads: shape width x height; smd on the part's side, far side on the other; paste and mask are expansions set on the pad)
"2 way 0.1\"" [mm] "two wire component!"
  round 1.905 hole 1: 1(-1.27,0) 2(1.27,0)
  silkscreen extent -2.67,-1.4 2.67,1.4
"9901 Relay" [mil] "SM reed relay"
  rect 100x25 smd: 1(-140,60) 2(140,60) 5(-140,-20) 6(140,-20)
  silkscreen extent -160,-100 160,100
BOLT [mm] "M3 mounting bolt"
  round 6 hole 3.2: 1(0,0)
  silkscreen extent -3.5,-3.5 3.5,3.5
"D Plug Straight PCB 9 Way" [mil] "D Plug Straight PCB 9 Way"
  round 75 hole 39.37: 1(-218,56) 2(-109,56) 3(0,56) 4(109,56) 5(218,56) 6(-163.5,-56) 7(-54.5,-56) 8(54.5,-56) 9(163.5,-56)
  round 275.59 hole 125.98: 10(-489,0) 10(489,0)
  silkscreen extent -564,-247 564,247
"D Socket Straight PCB 25 Way" [mil] "D socket Straight PCB 25 Way"
  round 75 hole 39.37: 1(654,56) 2(545,56) 3(436,56) 4(327,56) 5(218,56) 6(109,56) 7(0,56) 8(-109,56) 9(-218,56) 10(-327,56) 11(-436,56) 12(-545,56) 13(-654,56) 14(599.5,-56) 15(490.5,-56) 16(381.5,-56) 17(272.5,-56) 18(163.5,-56) 19(54.5,-56) 20(-54.5,-56) 21(-163.5,-56) 22(-272.5,-56) 23(-381.5,-56) 24(-490.5,-56) 25(-599.5,-56)
  round 275.59 hole 125.98: 26(-925,0) 26(925,0)
  silkscreen extent -1000,-247 1000,247
DO214AC [mm] "DO214AC"
  rect 2.5x1.8 smd: 1(-2.4,0) 2(2.4,0)
  silkscreen extent -4,-1.5 4,1.5
HS0805Long [mil] "0805 on big pads for hand soldering will also take 1206"
  rect 60x60 smd: 1(-50,0) 2(50,0)
  silkscreen extent -90,-40 90,40
hs0805long [mil] "0805 on big pads for hand soldering will also take 1206"
  rect 60x60 smd: 1(-50,0) 2(50,0)
  silkscreen extent -90,-40 90,40
HS1210 [mm] "Tant case B (A will also fit!)"
  rect 1.7x2.286 smd: 1(-1.625,0) 2(1.626,0)
  silkscreen extent -2.79,-1.52 3.18,1.52
"MKS2 7.2 8.5" [mm] "MKS2 7.2 by 8.5"
  round 1.905 hole 0.8: 1(-2.5,0) 2(2.5,0)
  silkscreen extent -3.75,-4.25 3.75,4.25
"MKS2 7.2 11" [mm] "MKS2 7.2 by 11 by 16"
  round 1.905 hole 0.8: 1(-2.5,0) 2(2.5,0)
  silkscreen extent -3.75,-5.5 3.75,5.5
"PCB SMB" [mm] "PCB mount SMB connector"
  round 2.54 hole 1.6: 1(0,0)
  round 2.54 hole 1.7: 2(-2.54,-2.54) 2(-2.54,2.54) 2(2.54,-2.54) 2(2.54,2.54)
  silkscreen extent -4.45,-4.45 4.45,4.45
"SM Test point" [mm] "SM Test point 100 x 100mil"
  rrect50% 2x2 smd: 1(0,0)
  silkscreen extent -1.5,-1.5 1.5,1.5
SOD123 [mm] "SOD123 Diode (500mW Zener etc)"
  rect 1.5x0.95 smd: 1(-1.875,0) 2(1.875,0)
  silkscreen extent -3,-1 3,1
"SOIC 8" [mil] "SOIC 8"
  rect 30x75 smd: 1(-75,-112.5) 2(-25,-112.5) 3(25,-112.5) 4(75,-112.5) 5(75,112.5) 6(25,112.5) 7(-25,112.5) 8(-75,112.5)
  silkscreen extent -100,-60 100,60
SpecialR [mil] "SM or TH"
  round 60 hole 31.5: 1(-200,0) 2(200,0)
  rect 60x60 smd: 1(-50,0) 2(50,0)
  silkscreen extent -250,-40 250,40
ww107 [mil] "Mini circuits MAR-6SM"
  rect 66x120 smd: 1(0,-107) 3(0,107)
  rect 25x25 hole 19.68: 2(25,0) 2(83,-47) 2(83,47) 2(138,-47) 2(138,0) 2(138,47) 4(-138,-47) 4(-138,0) 4(-138,47) 4(-83,-47) 4(-83,47) 4(-25,0)
  rect 60x40 smd: 2(77,0) 4(-77,0)
  Top Layer region: -158,70 -158,-70 -71,-70 -61,-60 -61,-25 -5,-25 -5,25 -61,25 -61,60 -71,70
  Top Layer region: 158,70 158,-70 71,-70 61,-60 61,-25 5,-25 5,25 61,25 61,60 71,70
  silkscreen extent -160,-175 160,175

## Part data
C1 C2 C3 C4 C5 C6 C7 C8 C9 C10 C11 C12 C13 C14 C15 C16 C17 C18 C19 C20 C21 C22 C23 C24 C25 C26 C27 C28 C29 C30 C31 C32 C33 C34 C35 C36 C37 C38 C39 C40 C41 C42 C43 C44 C45 C46 C47 C48 C49 C50 C51 C52 C53 C54 C55 C56 C57 C58: "Cap 0.2\" pitch"
D1 D3 D8 D9 D12 D14: library part "Sckottky Diode"
D2 D10 D11 D13: "TVS"
D4 D5 D6 D7 D15 D16 D17 D18: library part 1N4004
J1 J2: library part "PCB SMB"
U2 U6 U8 U12: library part DualOpAmp
U3 U4 U5 U9 U10 U11: library part SingleOpAmp

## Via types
v1: diameter 1.27, hole 0.8, Top Layer to Bottom Layer, 42 vias
v2: diameter 1.27, hole 0.711, Top Layer to Bottom Layer, 34 vias

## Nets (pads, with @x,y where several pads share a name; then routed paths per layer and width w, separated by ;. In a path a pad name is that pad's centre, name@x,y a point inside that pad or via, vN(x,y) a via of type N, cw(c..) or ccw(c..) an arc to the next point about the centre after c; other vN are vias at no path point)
+15V: C2.1 C4.1 C9.1 C10.1 C19.1 C22.1 C31.1 C33.1 C38.1 C39.1 C48.1 C51.1 C57.2 D8.1 R2.2 R26.2 U2.8 U3.7 U4.7 U5.7 U6.8 U8.8 U9.7 U10.7 U11.7 U12.8 U13.7 | length 491.1
  Top Layer w0.762: U9.7@77.153,117.475 C38.1@80.01,117.475 v2(81.915,117.475) ; U10.7@77.153,135.89 C39.1@80.645,135.89 v2(82.55,135.89) ; C51.1@77.47,160.02 v1(77.47,158.115) 77.47,156.845 78.105,156.21 U11.7@79.692,156.21 ; v1(83.82,96.774) 83.566,96.774 C31.1@83.566,94.742 R26.2@86.106,94.742 ; U12.8@93.662,157.48 93.662,158.433 93.98,158.75 C48.1@96.52,158.75 ; U8.8@105.093,157.48 105.093,158.433 105.41,158.75 C33.1@107.95,158.75 ; U2.8@119.062,157.48 119.062,158.686 v2(119.38,159.004) 119.634,158.75 C4.1@121.92,158.75 ; U6.8@130.493,157.48 133.35,157.48 ; v2(133.35,156.845) 133.35,157.48 ; C19.1@133.35,158.75 133.35,157.48 ; U5.7@142.558,156.21 144.272,156.21 144.78,156.718 C22.1@144.78,158.242 144.78,161.036 v1(145.034,161.29) ; U3.7@145.732,117.475 C9.1@148.59,117.475 v2(150.495,117.475) ; U4.7@145.732,135.89 C10.1@148.59,135.89 v2(150.495,135.89) ; C57.2@157.48,156.845 v1(157.48,152.4) U13.7@159.702,152.4
  Top Layer w1.27: D8.1@103.265,182.88 105.41,185.025 v1(105.41,185.166) ; R2.2@128.905,94.615 C2.1@131.445,94.615 v2(133.985,94.615)
  Dummy Power w0.762: v1(77.47,158.115) 86.995,158.115 88.011,159.131 v2(93.599,159.131) v2(105.029,159.131) 105.156,159.004 v2(119.38,159.004) 121.539,156.845 v2(133.35,156.845) 140.208,156.845 141.478,158.115 145.034,158.115 ; v2(81.915,117.475) v2(150.495,117.475) 152.4,117.475 ; v2(82.55,135.89) 82.55,141.605 84.455,143.51 148.59,143.51 ; v1(83.82,96.774) 84.201,97.155 131.445,97.155 v2(133.985,94.615) 141.605,94.615 152.4,105.41 152.4,117.475 ; 144.145,161.798 144.653,161.29 v1(145.034,161.29) 145.034,158.115 ; v1(157.48,152.4) 151.765,158.115 150.368,158.115 ; 145.034,158.115 150.368,158.115 ; 148.59,143.51 148.59,143.764 150.368,145.542 150.368,158.115 ; 148.59,143.51 148.59,135.89 v2(150.495,135.89) 150.495,133.35 152.4,131.445 152.4,117.475
  Dummy Power w1.016: v1(135.255,187.325) 144.145,178.435 144.145,161.798
  Bottom Layer w1.905: v1(105.41,185.166) 107.569,187.325 v1(135.255,187.325)
+15VIN: J3.8 J3.12 L5.1 X8.1 | length 36.9
  Top Layer w1.016: X8.1@84.303,186.69 L5.1@87.91,186.69 87.91,183.235 88.9,182.245 88.9,175.362 90.221,174.041 93.345,174.041 93.955,174.65 J3.12@93.955,176.068
  Dummy Ground w1.016: J3.12@93.955,176.068 93.955,174.65 94.615,173.99 104.14,173.99 105.029,174.879 J3.8@105.029,176.068
-15V: C15.1 C17.1 C18.1 C24.1 C27.1 C44.1 C46.1 C47.1 C53.1 C56.1 C58.1 D9.2 U2.4 U3.4 U4.4 U5.4 U6.4 U8.4 U9.4 U10.4 U11.4 U12.4 U13.4 | length 421.8
  Top Layer w0.635: C44.1@69.85,112.395 69.85,114.3 70.485,114.935 U9.4@71.438,114.935 ; U10.4@71.438,133.35 72.39,133.35 C46.1@72.39,130.81 ; U12.4@87.947,153.67 88.9,153.67 89.535,153.035 C56.1@89.535,151.13 v1(89.535,148.59) ; U8.4@99.377,153.67 100.33,153.67 C47.1@100.33,151.13 100.33,149.225 v2(99.695,148.59) ; U2.4@113.347,153.67 114.3,153.67 C18.1@114.3,151.13 114.3,149.225 v2(113.665,148.59) ; U6.4@124.777,153.67 126.365,153.67 C27.1@126.365,151.13 126.365,149.225 v2(125.73,148.59) ; v2(137.16,114.935) U3.4@140.017,114.935 140.335,114.617 C15.1@140.335,112.395 ; v2(137.16,133.35) U4.4@140.017,133.35 139.7,133.032 C17.1@139.7,130.81
  Top Layer w0.762: C53.1@70.485,146.685 73.025,146.685 73.977,147.637 v1(73.977,148.59) U11.4@73.977,153.67 ; U5.4@136.843,153.67 137.16,153.67 C24.1@137.16,151.13 v1(139.065,151.13) ; v1(142.24,151.13) 142.875,151.765 149.225,151.765 151.13,149.86 U13.4@153.987,149.86 156.21,149.86 156.845,149.225 C58.1@156.845,146.685
  Top Layer w1.016: v2(69.85,110.49) C44.1@69.85,112.395
  Top Layer w1.27: C46.1@72.39,130.81 v2(74.295,130.81) ; v1(110.49,183.515) D9.2@112.635,183.515
  Dummy Power w0.635: v2(99.695,148.59) 99.695,151.13 ; v2(113.665,148.59) 113.665,151.13 ; v2(125.73,148.59) 125.73,151.13
  Dummy Power w0.762: 72.39,149.86 72.707,149.86 v1(73.977,148.59) ; 74.295,143.51 73.977,143.827 v1(73.977,148.59) ; 75.565,148.59 v1(73.977,148.59) ; 100.33,114.3 101.6,115.57 127,115.57 130.175,112.395 ; 125.73,151.13 v1(139.065,151.13) v1(142.24,151.13)
  Dummy Power w1.27: v2(69.85,110.49) 69.85,114.3 ; 72.39,149.86 72.39,151.638 68.883,151.638 68.729,151.792 66.902,151.792 65.532,153.162 65.532,178.816 68.199,181.483 80.264,181.483 81.026,182.245 109.22,182.245 v1(110.49,183.515) ; 74.295,143.51 v2(74.295,130.81) 74.295,128.905 ; 75.565,148.59 v1(89.535,148.59) 91.44,148.59 93.98,151.13 99.695,151.13 113.665,151.13 125.73,151.13 ; 100.33,114.3 69.85,114.3 ; 130.175,112.395 136.525,112.395 137.16,113.03 v2(137.16,114.935) ; v2(137.16,133.35) 133.35,133.35 127,127 90.17,127 88.265,128.905 74.295,128.905 ; 69.85,114.3 69.85,116.205 74.295,120.65 74.295,128.905
-15VIN: J3.7 J3.11 L6.1 X9.1 | length 59
  Top Layer w1.016: L6.1@127.355,186.69 X9.1@131.293,186.69 132.842,186.69 v1(134.112,185.42)
  Dummy Power w1.016: J3.11@96.723,176.068 96.723,174.727 97.307,174.142 107.798,174.142 ; J3.7@107.798,176.068 107.798,174.142 ; v1(134.112,185.42) 133.858,185.42 132.588,184.15 128.27,184.15 127,182.88 127,179.317 126.98,179.297 126.98,175.704 127,175.684 127,175.26 125.73,173.99 121.427,173.99 121.25,174.168 115.748,174.168 113.843,172.263 109.677,172.263 107.798,174.142
BIASIN1: J3.6 L3.1 X3.1 | length 28.4
  Top Layer w0.305: v1(127,172.212) 127,171.958 127.508,171.45 X3.1@131.445,171.45
  Top Layer w0.508: X3.1@131.445,171.45 L3.1@134.62,171.45
  Bottom Layer w0.305: J3.6@110.566,176.068 110.566,173.279 111.125,172.72 118.745,172.72 120.015,171.45 126.238,171.45 v1(127,172.212)
BIASIN2: J3.10 L9.1 X13.1 | length 27.4
  Top Layer w0.305: L9.1@78.105,177.165 79.375,177.165 80.01,176.53 80.01,175.895 80.645,175.26 80.645,173.99 83.185,171.45 X13.1@84.15,171.45 86.36,171.45 86.995,172.085 93.98,172.085 95.885,173.99 98.425,173.99 99.492,175.057 J3.10@99.492,176.068
BIASMON1+: J3.3 R17.2 R19.2 | length 14.5
  Top Layer w0.305: J3.3@118.872,176.068 118.872,174.498 119.38,173.99 123.825,173.99 125.73,172.085 R17.2@125.73,169.545
  Top Layer w0.762: R17.2@125.73,169.545 R19.2@128.27,169.545
BIASMON1-: J3.15 R21.2 R23.2 | length 12.1
  Top Layer w0.305: R23.2@120.65,169.545 v1(120.65,172.72)
  Top Layer w0.762: R23.2@120.65,169.545 R21.2@123.19,169.545
  Bottom Layer w0.203: 120.256,174.866 J3.15@120.256,178.913
  Bottom Layer w0.305: 120.256,174.866 120.65,174.473 v1(120.65,172.72)
BIASMON2+: J3.5 R41.2 R43.2 | length 25.5
  Top Layer w0.305: R43.2@95.25,169.545 95.25,170.815 97.155,172.72 112.395,172.72 113.335,173.66 J3.5@113.335,176.068
  Top Layer w0.762: R41.2@92.71,169.545 R43.2@95.25,169.545
BIASMON2-: J3.17 R45.2 R47.2 | length 34
  Top Layer w0.305: R45.2@90.17,169.545 90.17,170.815 90.805,171.45 94.615,171.45 96.52,173.355 111.125,173.355 v1(111.76,173.99)
  Top Layer w0.762: R47.2@87.63,169.545 R45.2@90.17,169.545
  Bottom Layer w0.203: 114.719,175.044 J3.17@114.719,178.913
  Bottom Layer w0.305: v1(111.76,173.99) 113.665,173.99 114.719,175.044
GND: Bolt1.1 Bolt2.1 Bolt3.1 Bolt4.1 C2.2 C4.2 C5.2 C9.2 C10.2 C15.2 C17.2 C18.2 C19.2 C21.1 C22.2 C24.2 C27.2 C28.2 C29.2 C31.2 C33.2 C34.2 C38.2 C39.2 C44.2 C46.2 C47.2 C48.2 C50.1 C51.2 C53.2 C56.2 C57.1 C58.2 D2.2 D3.2 D6.2 D7.1 D10.1 D11.1 D13.2 D14.2 D17.2 D18.1 D19.2 D20.2 J1.2 J2.2 J3.1 J3.4 J3.16 J3.19 J3.20 J3.23 J3.24 J3.26 J4.3 J4.6 J4.7 J4.8 J4.9 J4.10 L4.1 L10.1 R24.1 R48.1 R53.1 R54.1 RL1.2 RL2.2 U1.2 U1.4 U2.3 U3.3 U4.3 U6.3 U7.2 U7.4 U8.3 U9.3 U10.3 U12.3 U13.5 X10.1 | length 407.9
  Top Layer w0.305: v2(68.58,133.985) 69.215,134.62 U10.3@71.438,134.62 ; U9.3@71.438,116.205 73.66,116.205 74.295,115.57 v2(74.295,112.395) ; C56.2@86.995,151.13 86.995,152.4 86.36,153.035 86.36,154.94 U12.3@87.947,154.94 ; C47.2@97.79,151.13 97.79,154.94 U8.3@99.377,154.94 ; C18.2@111.76,151.13 111.76,154.94 U2.3@113.347,154.94 ; C27.2@123.825,151.13 123.825,151.765 123.19,152.4 123.19,154.94 U6.3@124.777,154.94 ; J3.1@124.409,176.068 124.535,176.068 125.342,175.26 128.179,175.26 130.409,177.49 J3.26@131.293,177.49 ; v2(133.985,115.189) 135.001,116.205 U3.3@140.017,116.205 ; 135.89,130.81 135.89,133.985 136.525,134.62 U4.3@140.017,134.62
  Top Layer w0.381: RL2.2@105.791,118.364 105.791,119.126 v1(106.68,120.015) ; v1(121.92,120.65) 122.301,120.269 RL1.2@122.301,118.364
  Top Layer w0.762: D17.2@67.945,101.74 67.945,98.425 74.53,91.84 L10.1@74.53,89.535 ; v2(68.58,169.545) 70.98,169.545 71.12,169.685 74.435,169.685 74.93,170.18 D14.2@74.93,170.845 ; C39.2@80.645,138.43 v2(80.645,140.335) ; v1(80.645,168.91) C34.2@80.645,170.815 ; C31.2@83.566,92.202 83.566,89.154 83.82,88.9 89.383,88.9 J2.2@90.018,88.265 ; v2(85.09,150.495) 85.725,151.13 C56.2@86.995,151.13 ; C48.2@96.52,161.29 v2(98.425,161.29) ; v2(97.155,148.59) 97.79,149.225 C47.2@97.79,151.13 ; v2(106.68,161.29) C33.2@107.95,161.29 ; v2(111.125,149.225) 111.76,149.86 C18.2@111.76,151.13 ; v2(120.015,161.29) C4.2@121.92,161.29 ; v2(123.19,149.225) 123.825,149.86 C27.2@123.825,151.13 ; v1(130.81,162.56) 130.81,162.306 131.102,162.014 C19.2@132.715,162.014 ; J3.26@131.293,177.49 133.493,175.29 D3.2@138.43,175.29 141.08,175.29 D2.2@141.287,175.082 ; v2(133.985,115.189) D7.1@133.985,112.255 134.125,112.395 C15.2@137.795,112.395 ; v1(133.985,153.67) 133.985,151.765 C24.2@134.62,151.13 ; v2(135.255,130.81) 135.89,130.81 C17.2@137.16,130.81 ; L4.1@138.525,89.535 138.525,87.535 139.192,86.868 142.748,86.868 144.145,88.265 D6.2@144.145,97.93 ; C5.2@141.605,172.085 D2.2@141.605,175.4 ; C22.2@147.32,158.242 147.32,155.23 C21.1@147.65,154.9 150.455,154.9 152.4,156.845 R24.1@152.4,158.242 ; C9.2@148.59,120.015 v2(150.495,120.015) ; C10.2@148.59,138.43 150.495,138.43 v2(151.13,139.065) ; v1(152.4,146.685) C58.2@154.305,146.685 154.305,145.415 154.94,144.78 158.75,144.78 159.702,145.732 U13.5@159.702,149.86 ; C57.1@157.48,159.385 C57.1@157.48,159.512 v1(157.48,162.306)
  Top Layer w1.016: C53.2@67.945,146.685 C50.1@67.945,149.9 ; v2(68.58,133.985) 68.58,132.08 C46.2@69.85,130.81 ; C44.2@72.39,112.395 v2(74.295,112.395) ; C51.2@77.47,162.56 78.74,162.56 v1(79.375,161.925) ; R48.1@79.375,151.13 v1(81.915,151.13) ; C38.2@80.01,120.015 v2(81.915,120.015) ; D18.1@83.185,106.54 84.595,106.54 v2(86.36,104.775) ; C28.2@93.98,183.515 95.339,182.156 J3.24@95.339,178.913 ; D20.2@94.615,113.805 94.615,111.76 v1(95.885,110.49) ; D10.1@100.19,186.69 X10.1@107.798,186.69 ; J3.20@106.413,178.913 106.413,180.34 106.426,180.34 107.798,181.712 X10.1@107.798,186.69 ; v1(107.95,113.03) 110.35,113.03 D19.2@111.125,113.805 ; J3.16@117.488,178.913 117.488,180.353 118.11,180.975 125.73,180.975 126.225,181.47 D11.1@126.225,182.88 ; C29.2@118.11,186.69 X10.1@107.798,186.69 ; J1.2@125.578,88.265 129.54,88.265 131.445,90.17 C2.2@131.445,92.075 ; v1(151.638,168.656) 152.908,167.386 R53.1@154.432,167.386 R54.1@156.972,167.386
  Dummy Ground w0.381: J3.26@84.303,179.553 J3.26@84.303,177.49 87.643,180.83 87.643,180.962 117.488,180.962 ; J3.4@116.103,176.068 116.103,177.528 J3.16@117.488,178.913 117.488,180.962 ; J3.26@131.293,177.49 127.821,180.962 117.488,180.962
  Dummy Ground w0.762: v1(130.81,162.56) 130.81,156.21 133.35,153.67 v1(133.985,153.67) 133.985,151.765 139.065,146.685 v1(152.4,146.685) ; C21.1@147.65,154.9 153.63,154.9 153.63,158.456 v1(157.48,162.306)
  Dummy Ground w1.016: C50.1@67.945,149.9 69.175,151.13 v1(81.915,151.13) ; v1(79.375,161.925) 78.105,163.195 78.105,166.37 v1(80.645,168.91) ; v1(151.638,168.656) 151.638,168.148 v1(157.48,162.306)
NetC1_2: C1.2 U1.1 | length 3.6
  Top Layer w0.635: U1.1@123.19,104.953 C1.2@123.19,108.585
NetC3_1: C3.1 L1.1 U1.3 | length 7.7
  Top Layer w0.508: C3.1@122.555,94.615 C3.1@123.19,95.25 ; U1.3@123.19,99.517 C3.1@123.19,95.25 ; L1.1@125.73,95.25 C3.1@123.19,95.25
NetC3_2: C3.2 J1.1 X2.1 | length 13.1
  Top Layer w0.508: C3.2@122.555,92.075 123.038,91.592 J1.1@123.038,85.725 X2.1@129.54,85.725
NetC6_1: C6.1 R5.1 R8.2 R11.2 R49.1 U3.2 | length 36.3
  Top Layer w0.305: R5.1@137.795,122.555 R5.1@141.605,122.555 ; U3.2@140.017,117.475 141.605,117.475 ; C6.1@141.605,127.635 R49.1@141.605,125.095 R5.1@141.605,122.555 ; R8.2@151.892,105.41 R11.2@151.892,108.585 ; R11.2@151.892,108.712 R11.2@151.892,108.585 ; 141.605,117.475 142.24,118.11 142.24,120.015 141.605,120.65 R5.1@141.605,122.555 ; 141.605,117.475 142.24,116.84 142.24,111.76 145.415,108.585 R11.2@151.892,108.585
NetC6_2: C6.2 R5.2 R9.1 R12.1 R49.2 U3.6 X5.1 | length 35.3
  Top Layer w0.305: U3.6@145.732,116.205 144.145,116.205 143.51,116.84 143.51,120.015 144.145,120.65 R5.2@144.145,122.555 ; R5.2@147.955,122.555 R5.2@144.145,122.555 ; X5.1@148.285,127 148.59,127.305 X5.1@148.59,127.635 ; R12.1@148.59,132.715 148.59,129.54 X5.1@148.59,127.635 ; R9.1@151.765,127.635 C6.2@144.145,127.635 ; R5.2@144.145,122.555 R49.2@144.145,125.095 C6.2@144.145,127.635 ; C6.2@144.145,127.635 X5.1@148.59,127.635
NetC7_1: C7.1 R50.2 | length 2.5
  Top Layer w0.305: R50.2@139.065,142.24 C7.1@141.605,142.24
NetC7_2: C7.2 R4.1 R6.2 R13.1 U2.5 U4.6 X4.1 | length 62.1
  Top Layer w0.305: R13.1@110.49,153.67 110.49,152.4 109.855,151.765 109.855,146.685 110.49,146.05 X4.1@112.725,146.05 118.11,146.05 118.745,146.685 ; U2.5@119.062,153.67 119.38,153.352 R4.1@119.38,151.13 119.38,148.59 118.745,147.955 118.745,146.685 ; U4.6@145.732,134.62 144.145,134.62 143.51,135.255 143.51,137.795 144.145,138.43 R6.2@144.145,139.7 C7.2@144.145,142.24 144.145,144.145 142.875,145.415 121.285,145.415 120.015,146.685 118.745,146.685
NetC8_1: C8.1 R3.1 R4.2 U2.6 | length 18.6
  Top Layer w0.305: R3.1@115.57,167.005 C8.1@115.57,164.465 115.57,161.925 116.205,161.29 116.205,155.575 116.84,154.94 ; R4.2@116.84,151.13 116.84,154.94 ; U2.6@119.062,154.94 116.84,154.94
NetC8_2: C8.2 R7.1 U2.7 | length 13.2
  Top Layer w0.305: R7.1@118.11,167.005 C8.2@118.11,164.465 118.11,162.56 116.84,161.29 116.84,156.845 117.475,156.21 U2.7@119.062,156.21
